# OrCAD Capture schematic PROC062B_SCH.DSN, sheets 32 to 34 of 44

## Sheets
32 31. FT4232 UART TO USB BRIDGE: size C; title: FT4232 UART TO USB BRIDGE
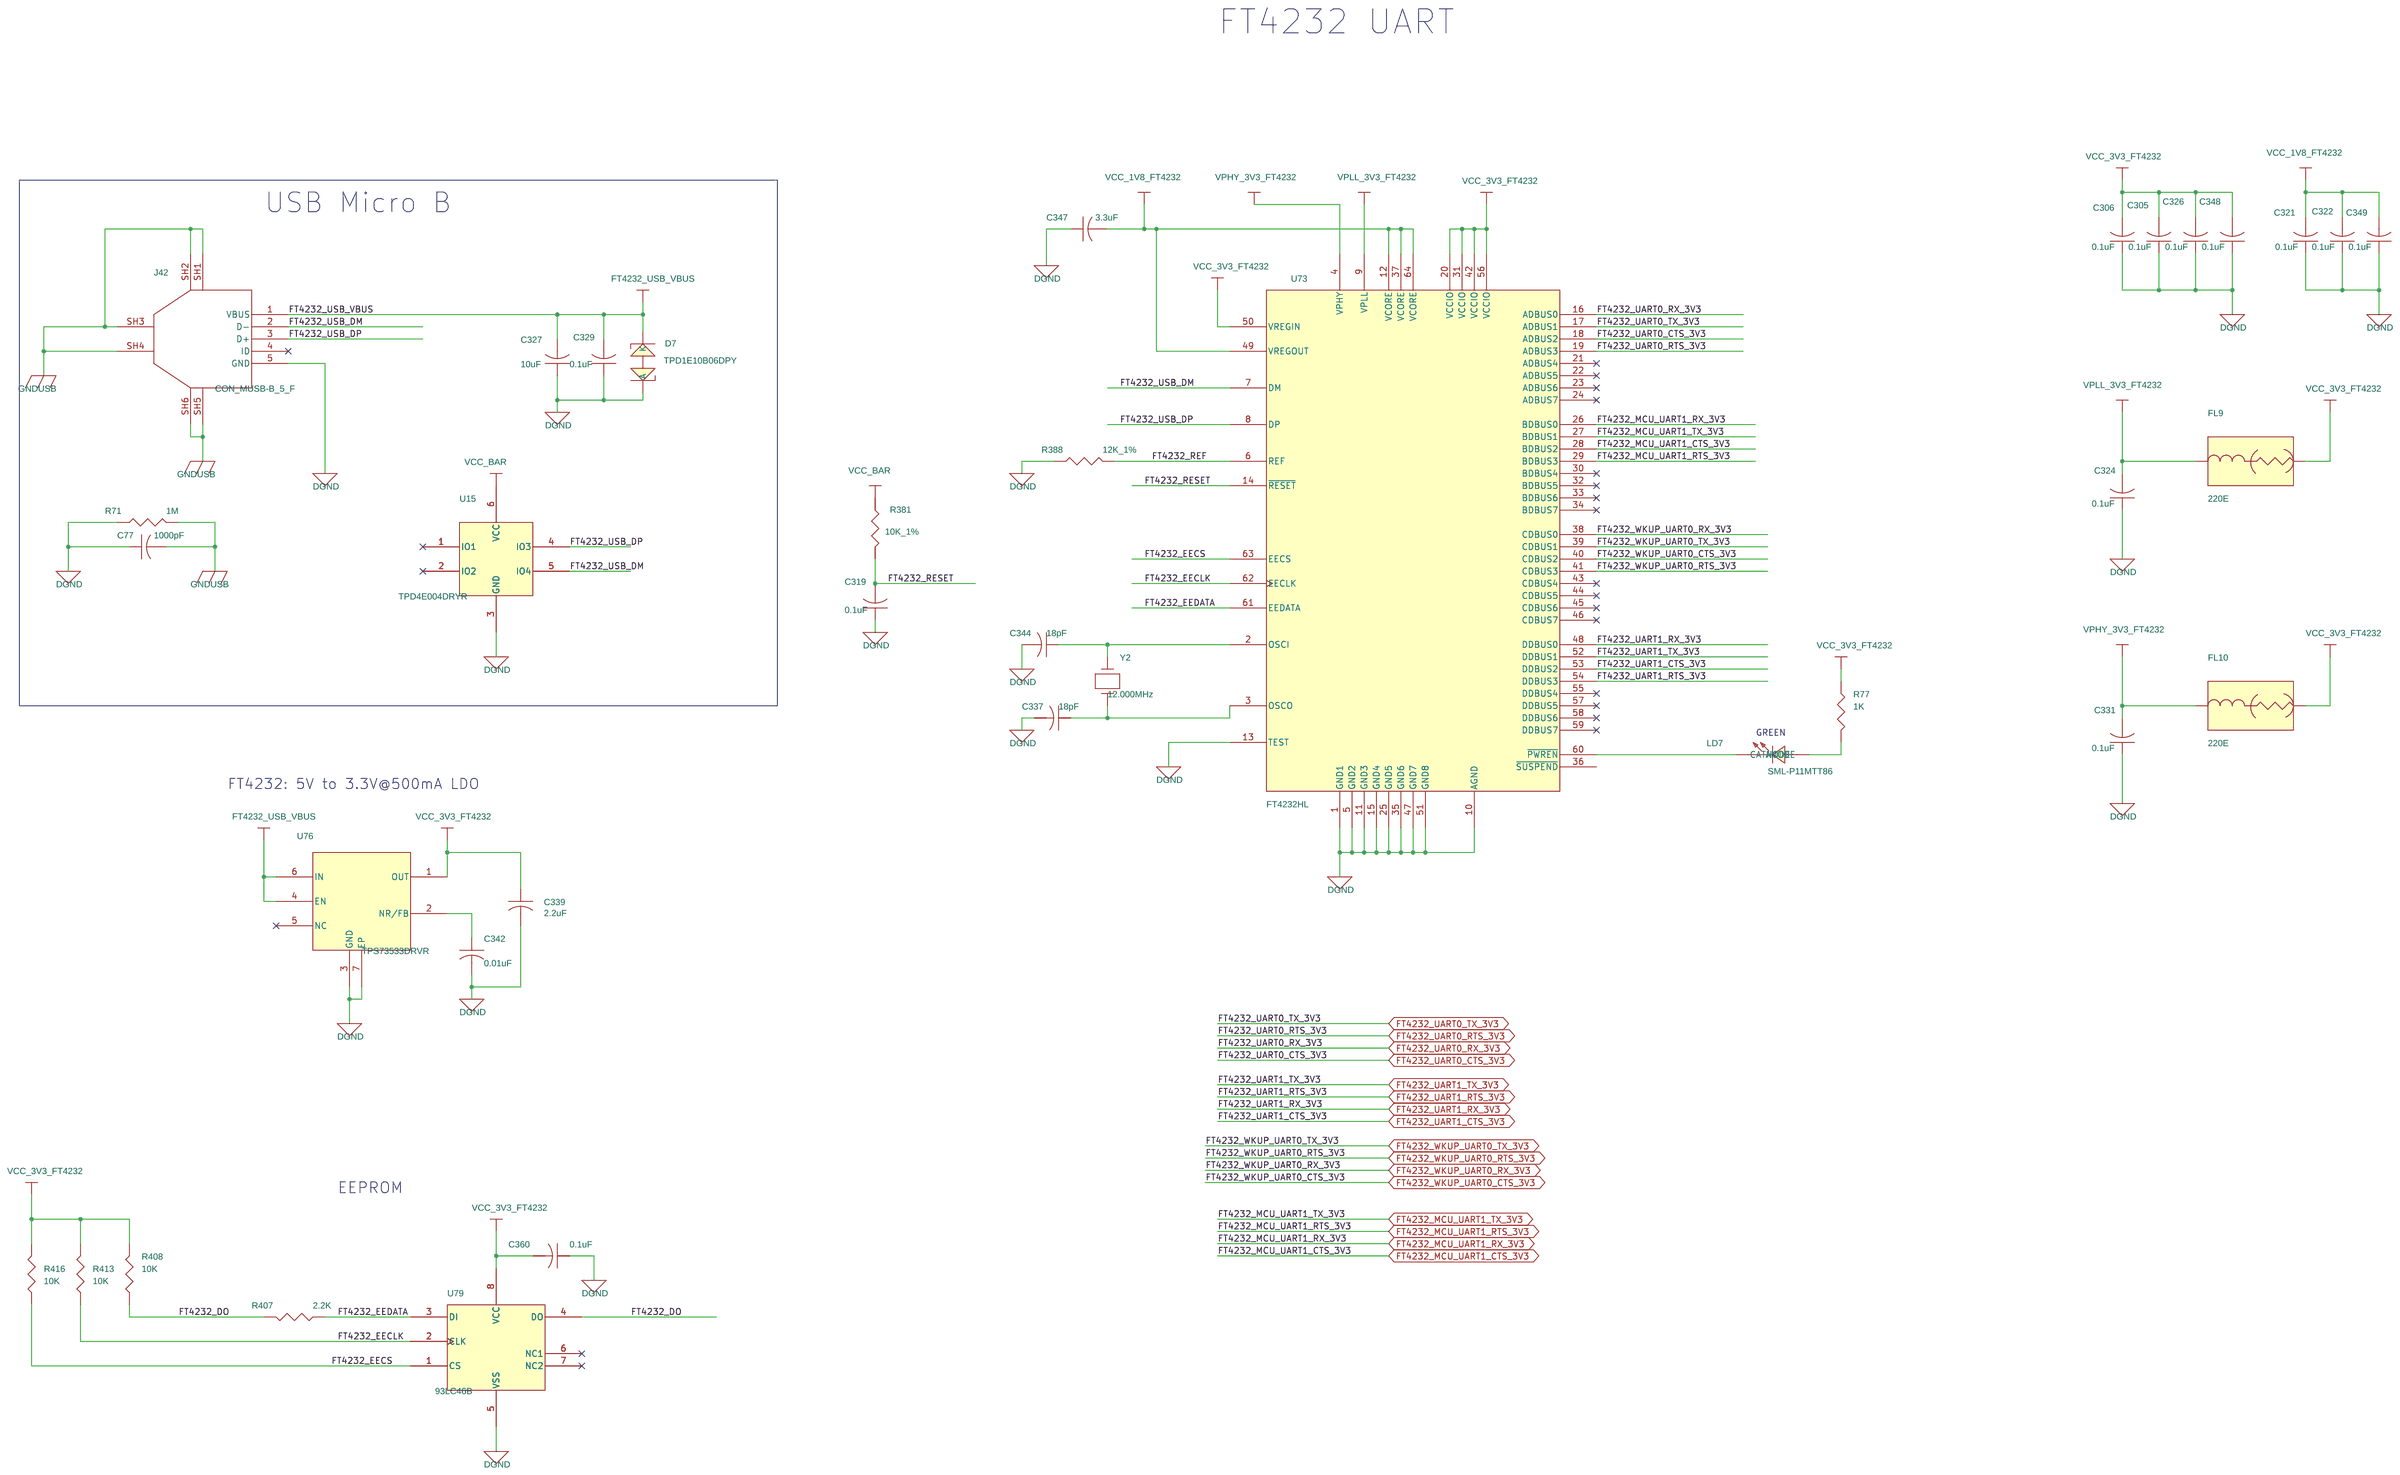
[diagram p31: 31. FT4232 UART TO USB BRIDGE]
33 32.APPLICATION BOARD CONN: size C; title: APPLICATION BOARD CONNECTOR
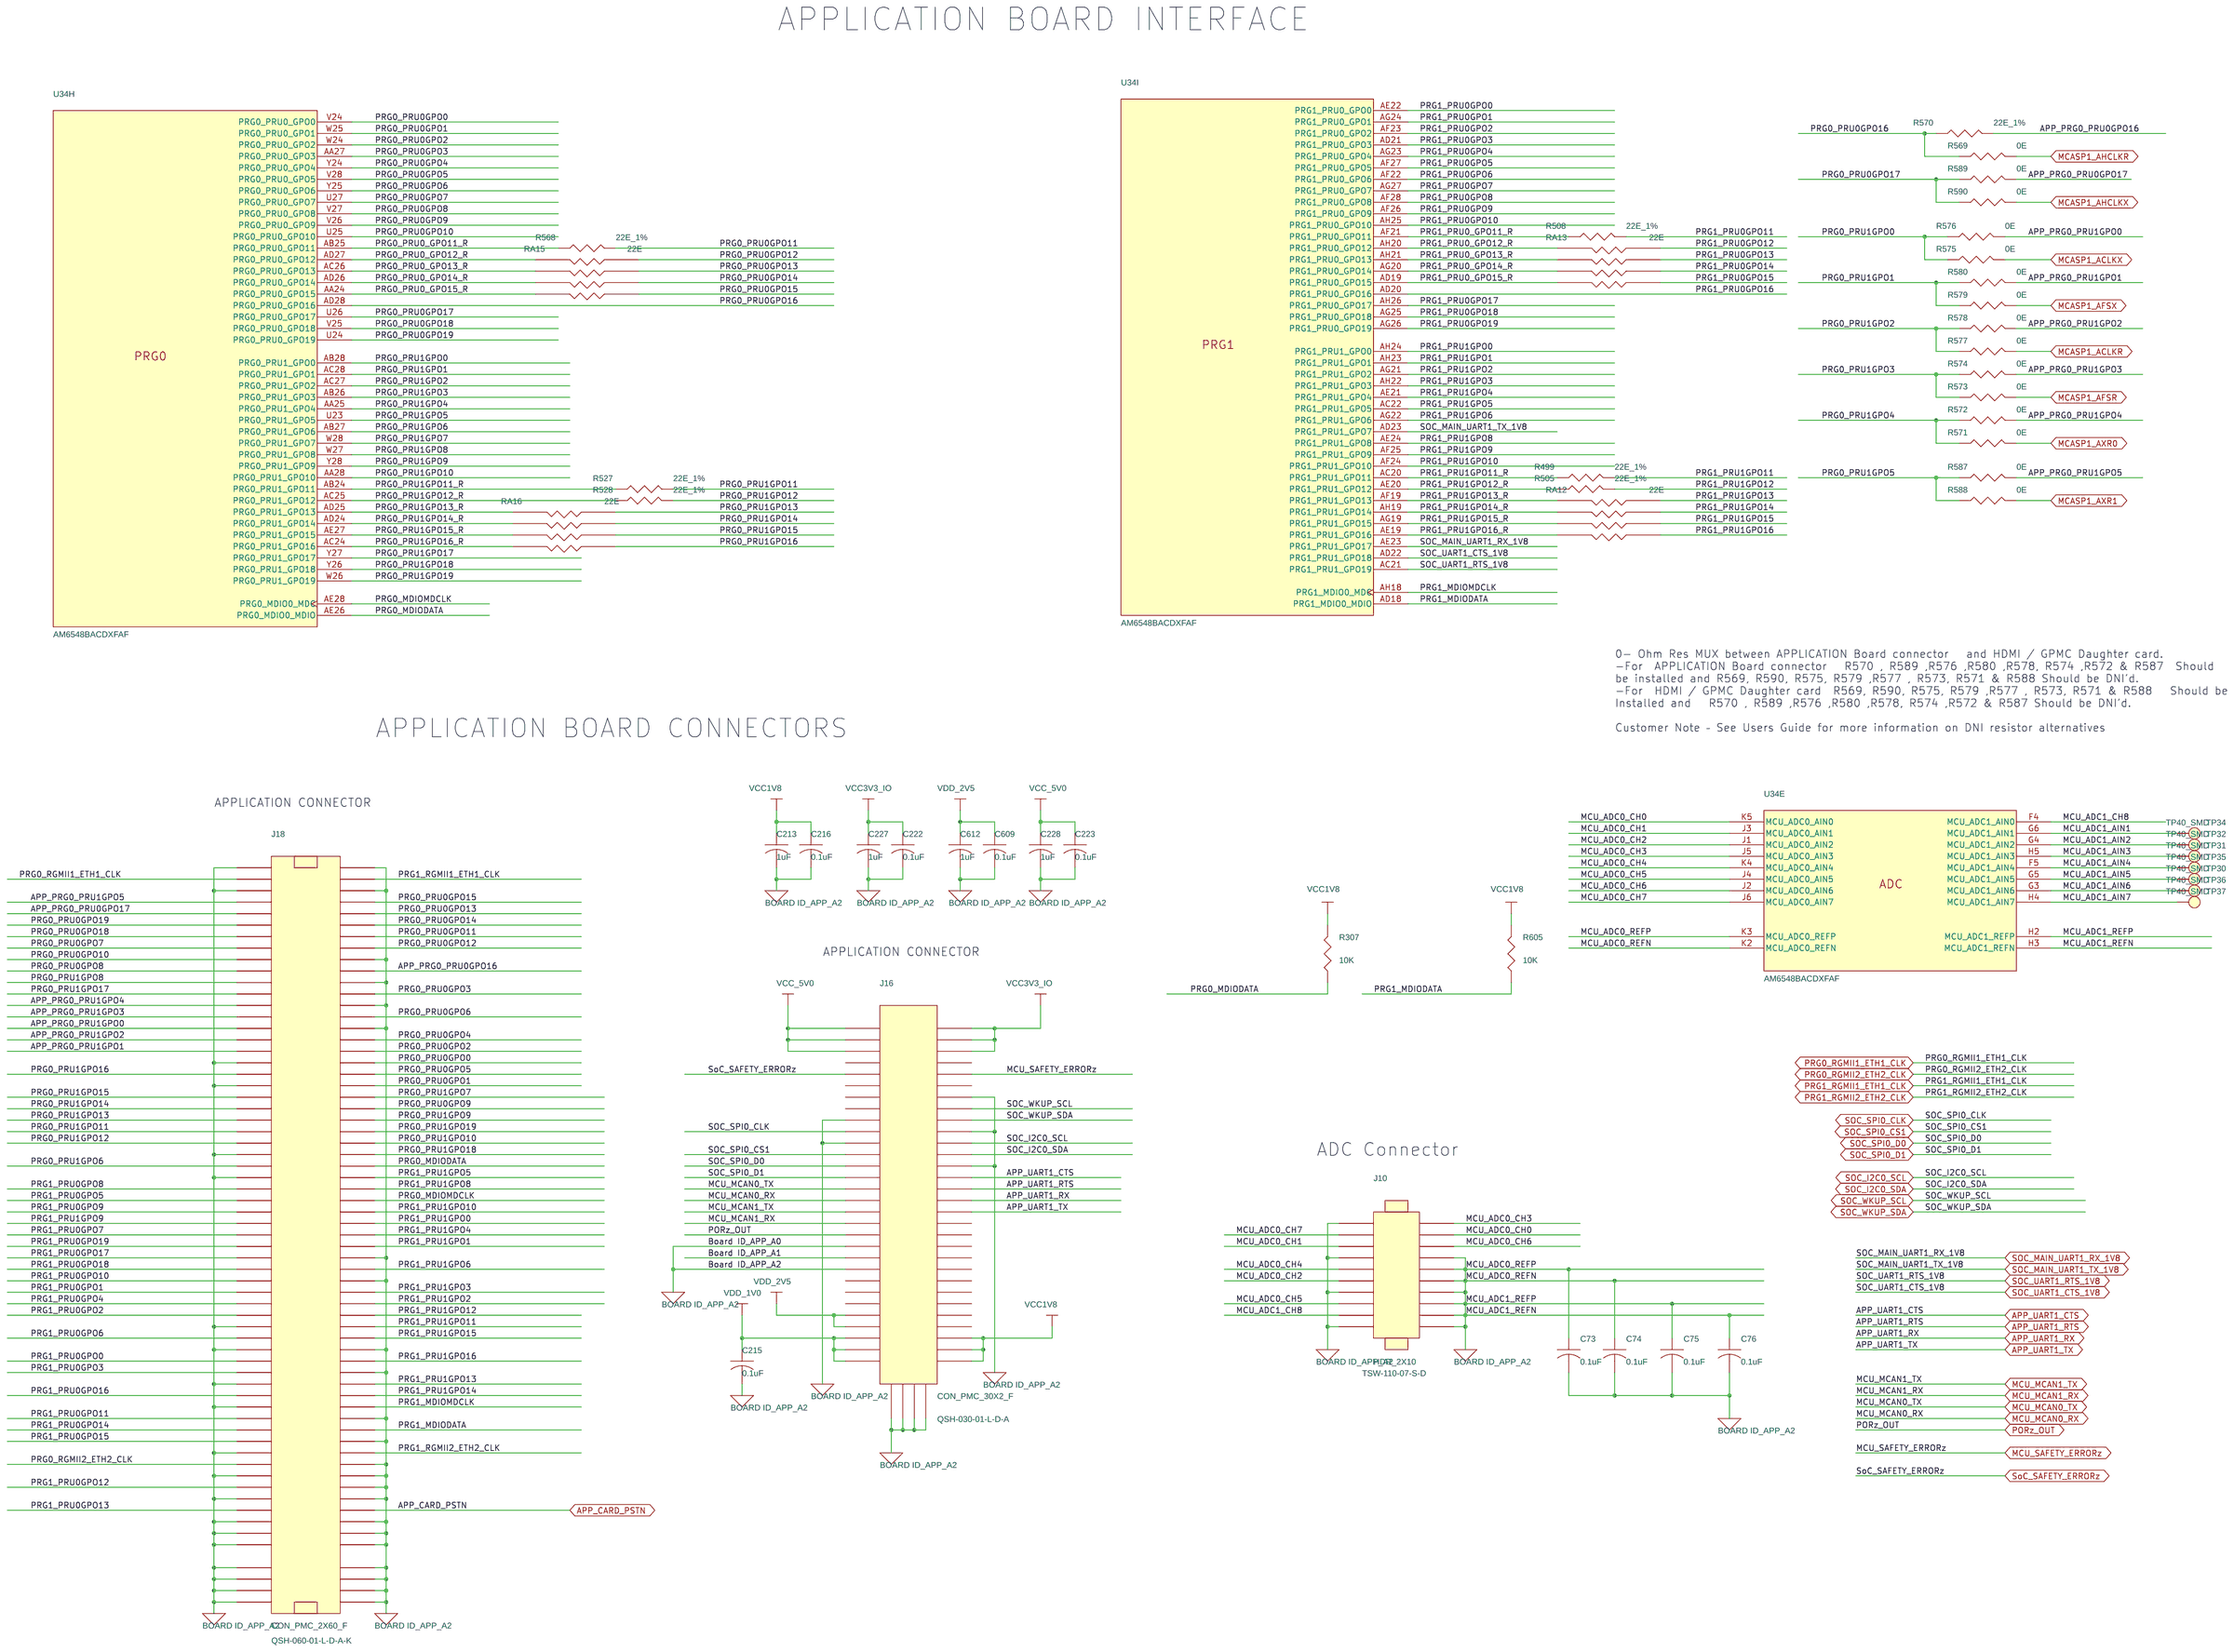
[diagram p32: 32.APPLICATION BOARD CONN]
34 33. GENERAL & MCU_GENERAL INTER: size C; title: SOC_GENERAL & MCU GENERAL
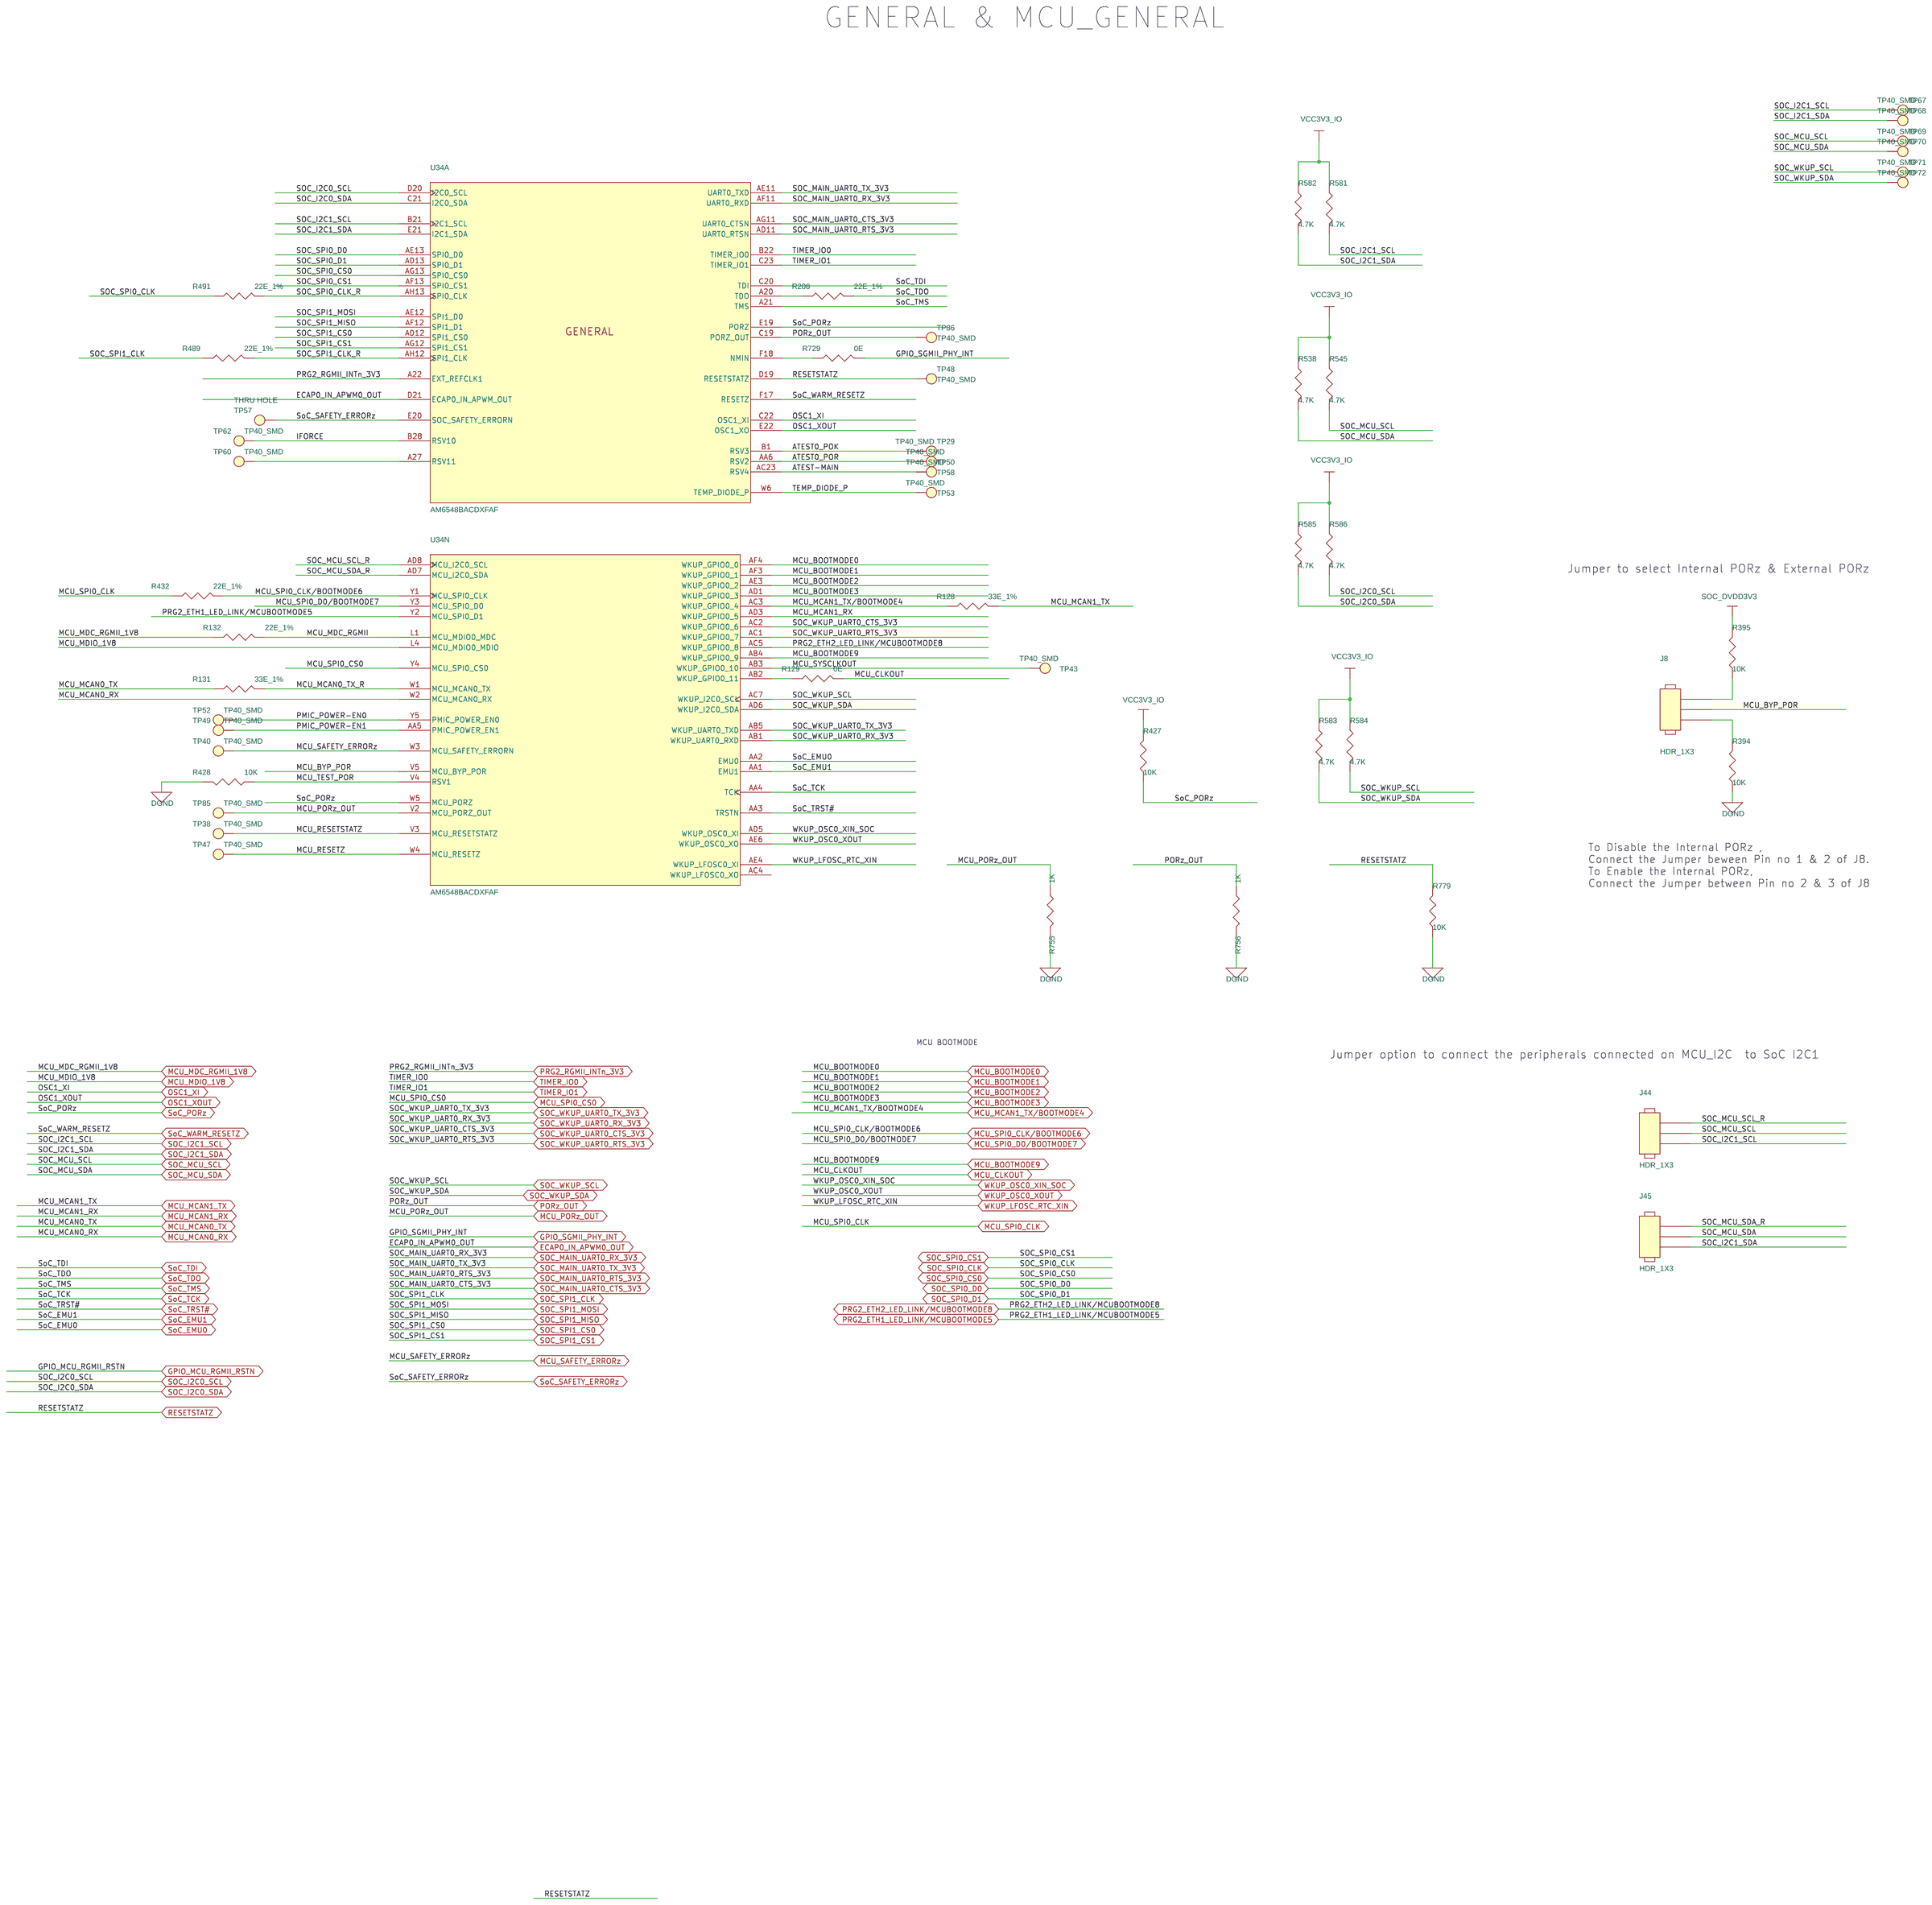
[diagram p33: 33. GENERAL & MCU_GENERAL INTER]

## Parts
sheet 16. DDR4 ECC & TERMINATIONS
U34  AM6548BACDXFAF  [BGA784_31-49_910X910_1-7]  (sections A,B,C,D,E,F,G,H,I,J,K,L,M,N,O,P,Q,R,S)
sheet 31. FT4232 UART TO USB BRIDGE
C77  1000pF  [CAP1206]
C305  0.1uF  [CAP0201_0-5]
C306  0.1uF  [CAP0201_0-5]
C319  0.1uF  [CAP0201_0-5]
C321  0.1uF  [CAP0201_0-5]
C322  0.1uF  [CAP0201_0-5]
C324  0.1uF  [CAP0201_0-5]
C326  0.1uF  [CAP0201_0-5]
C327  10uF  [CAP0603_1]
C329  0.1uF  [CAP0201_0-5]
C331  0.1uF  [CAP0201_0-5]
C337  18pF  [CAP0402_0-75]
C339  2.2uF  [CAP0402_0-75]
C342  0.01uF  [CAP0201_0-5]
C344  18pF  [CAP0402_0-75]
C347  3.3uF  [CAP0402]
C348  0.1uF  [CAP0201_0-5]
C349  0.1uF  [CAP0201_0-5]
C360  0.1uF  [CAP0201_0-5]
D7  TPD1E10B06DPY  [DIO_DFN0402]
FL9  220E  [EMIFIL_BLM15A_0402]
FL10  220E  [EMIFIL_BLM15A_0402]
J42  CON_MUSB-B_5_F  [CON_MUSBB5_1051640001_S_R_S_2-5]
LD7  SML-P11MTT86  [LED_0402_0-3]
R71  1M  [RES0603_0-75]
R77  1K  [RES0201]
R381  10K_1%  [RES0402_0-5]
R388  12K_1%  [RES0402]
R407  2.2K  [RES0402_0-5]
R408  10K  [RES0402_0-5]
R413  10K  [RES0402_0-5]
R416  10K  [RES0402_0-5]
U15  TPD4E004DRYR  [SON6_19-68_60X45]
U73  FT4232HL  [LQFP64_19-68_390X390_1-6]
U76  TPS73533DRVR  [SON6_25-59_85X85]
U79  93LC46B  [MSOP8_25-59_125X125_1-1]
Y2  12.000MHz  [XTAL_ABM3_205X130_SMD_1-4]
sheet 32.APPLICATION BOARD CONN
C73  0.1uF  [CAP0201_0-5]
C74  0.1uF  [CAP0201_0-5]
C75  0.1uF  [CAP0201_0-5]
C76  0.1uF  [CAP0201_0-5]
C213  1uF  [CAP0402_0-75]
C215  0.1uF  [CAP0201_0-5]
C216  0.1uF  [CAP0201_0-5]
C222  0.1uF  [CAP0201_0-5]
C223  0.1uF  [CAP0201_0-5]
C227  1uF  [CAP0402_0-75]
C228  1uF  [CAP0402_0-75]
C609  0.1uF  [CAP0201_0-5]
C612  1uF  [CAP0402_0-75]
J10  HDR_2X10  [HDR_2X10_TSW_100_S_T]
J16  CON_PMC_30X2_F  [CON_PMC30X2_QSH-030-01-L_S_S_S]
J18  CON_PMC_2X60_F  [CON_PMC60X2_HQCD-060_S_S_S_3-3]
R307  10K  [RES0402_0-5]
R499  22E_1%  [RES0402]
R505  22E_1%  [RES0402]
R508  22E_1%  [RES0402]
R527  22E_1%  [RES0402]
R528  22E_1%  [RES0402]
R568  22E_1%  [RES0402]
R569  0E  [RES0402_0-5]
R570  22E_1%  [RES0402]
R571  0E  [RES0402_0-5]
R572  0E  [RES0402_0-5]
R573  0E  [RES0402_0-5]
R574  0E  [RES0402_0-5]
R575  0E  [RES0402_0-5]
R576  0E  [RES0402_0-5]
R577  0E  [RES0402_0-5]
R578  0E  [RES0402_0-5]
R579  0E  [RES0402_0-5]
R580  0E  [RES0402_0-5]
R587  0E  [RES0402_0-5]
R588  0E  [RES0402_0-5]
R589  0E  [RES0402_0-5]
R590  0E  [RES0402_0-5]
R605  10K  [RES0402_0-5]
RA12  22E  [RESA_EXB28V_0402-4_0-5]
RA13  22E  [RESA_EXB28V_0402-4_0-5]
RA15  22E  [RESA_EXB28V_0402-4_0-5]
RA16  22E  [RESA_EXB28V_0402-4_0-5]
TP30  TP40_SMD  [TP40_SMD]
TP31  TP40_SMD  [TP40_SMD]
TP32  TP40_SMD  [TP40_SMD]
TP34  TP40_SMD  [TP40_SMD]
TP35  TP40_SMD  [TP40_SMD]
TP36  TP40_SMD  [TP40_SMD]
TP37  TP40_SMD  [TP40_SMD]
sheet 33. GENERAL & MCU_GENERAL INTER
J8  HDR_1X3  [HDR_3X1_100_S_T]
J44  HDR_1X3  [HDR_3X1_100_S_T]
J45  HDR_1X3  [HDR_3X1_100_S_T]
R128  33E_1%  [RES0402_0-5]
R129  0E  [RES0402_0-5]
R131  33E_1%  [RES0402_0-5]
R132  22E_1%  [RES0402]
R208  22E_1%  [RES0402]
R394  10K  [RES0402_0-5]
R395  10K  [RES0402_0-5]
R427  10K  [RES0402_0-5]
R428  10K  [RES0402_0-5]
R432  22E_1%  [RES0402]
R489  22E_1%  [RES0402]
R491  22E_1%  [RES0402]
R538  4.7K  [RES0402]
R545  4.7K  [RES0402]
R581  4.7K  [RES0402]
R582  4.7K  [RES0402]
R583  4.7K  [RES0402]
R584  4.7K  [RES0402]
R585  4.7K  [RES0402]
R586  4.7K  [RES0402]
R729  0E  [RES0402_0-5]
R755  1K  [RES0402]
R756  1K  [RES0402]
R779  10K  [RES0402_0-5]
TP29  TP40_SMD  [TP40_SMD]
TP38  TP40_SMD  [TP40_SMD]
TP40  TP40_SMD  [TP40_SMD]
TP43  TP40_SMD  [TP40_SMD]
TP47  TP40_SMD  [TP40_SMD]
TP48  TP40_SMD  [TP40_SMD]
TP49  TP40_SMD  [TP40_SMD]
TP50  TP40_SMD  [TP40_SMD]
TP52  TP40_SMD  [TP40_SMD]
TP53  TP40_SMD  [TP40_SMD]
TP57  THRU HOLE  [TP_40X65]
TP58  TP40_SMD  [TP40_SMD]
TP60  TP40_SMD  [TP40_SMD]
TP62  TP40_SMD  [TP40_SMD]
TP67  TP40_SMD  [TP40_SMD]
TP68  TP40_SMD  [TP40_SMD]
TP69  TP40_SMD  [TP40_SMD]
TP70  TP40_SMD  [TP40_SMD]
TP71  TP40_SMD  [TP40_SMD]
TP72  TP40_SMD  [TP40_SMD]
TP85  TP40_SMD  [TP40_SMD]
TP86  TP40_SMD  [TP40_SMD]

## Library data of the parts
U34 = AM654X_BGA784: IC AM65X MICRO CONTROLLER UNIT BGA784; Chkd/date: ALVY/010721; Crtd /date: MANIRAJA/010721; Custom_Duty: 15%; Customs_HS_Code: 85423100; Distributor_name: NA; Distributor_part_number: NA; Footprint Path: Y:\MIS_DATABASE\Library\ALTIUM_TOOL\PCB_FOOTPRINTS\Altium_Footprint_Lib.PcbLib; Height: 1.63MM; Library Path: Y:\MIS_DATABASE\Library\ALTIUM_TOOL\SCHEMATICS_PARTS\MS_MICROCONTROLLER_Library.schlib; Mfr_name: TEXAS INSTRUMENTS; Mistral Part No: 141221070001; Package: BGA784; Part_type: ICS\DIGITAL\MICROCONTROLLER; Project: TI_AM65X_CP; RoHS: NA; Temperature: NA; Tolerance: NA; Voltage: NA; Wattage: NA; Weight: NA; Datasheet: Y:\MIS_DATABASE\DATASHEETS\ICS\DIGITAL\MICROCONTROLLER\MAXWELLM4.PDF
C77 = CAP: CAP CERAMIC 1000pF 2KV 10% X7R 1206; Chkd/date: SHREESHAIL/291106; Crtd /date: MAZHAR/281106; Custom_Duty: 15%; Customs_HS_Code: 85322990; Distributor_name: DIGIKEY; Distributor_part_number: 478-2956-1-ND; Footprint Path: Y:\MIS_DATABASE\Library\ALTIUM_TOOL\PCB_FOOTPRINTS\Altium_Footprint_Lib.PcbLib; Height: 1.50MM; Library Path: Y:\MIS_DATABASE\Library\ALTIUM_TOOL\SCHEMATICS_PARTS\MS_DISCRETE_Library.schlib; Mfr_name: AVX CORPORATION; Mfr_part_number: 1206GC102KAT1A; Mistral Part No: 120009030147-R; Package: 1206; Part_type: CAPACITORS\CERAMIC; Project: ADR1B; RoHS: RoHS; Temperature: -55°C+125°C; Tolerance: 10%; Voltage: 2KV; Weight: NA; Datasheet: Y:\MIS_DATABASE\DATASHEETS\CAPACITORS\AVX_MLC.PDF
C73-C76 C215 C216 C222 C223 C305 C306 C319 C321 C322 C324 C326 C329 C331 C348 C349 C360 C609 = CAP: CAP CERAMIC 0.1uF 16V 10% X5R 0201; Chkd/date: MANIRAJA/120218; Crtd /date: MANIRAJA/120218; Custom_Duty: 15%; Customs_HS_Code: 85322990; Distributor_name: DIGIKEY; Distributor_part_number: 490-16742-1-ND; Height: 0.33MM; Mfr_name: MURATA; Mfr_part_number: GRM033R61C104KE84J; Mistral Part No: 120009030072-R; Package: 0201; Part_type: CAPACITORS\CERAMIC; Project: TI_MAXIE_CPB; RoHS: RoHS; Temperature: -55°C+85°C; Tolerance: 10%; Voltage: 16V; Wattage: NA; Weight: 0.33mg; Datasheet: Y:\MIS_DATABASE\DATASHEETS\CAPACITORS\GRM033R61C104KE84.PDF
C327 = CAP: CAP CERAMIC 10uF 10V 10% X5R 0603; Chkd/date: MANIRAJA/230118; Crtd /date: MANIRAJA/230118; Custom_Duty: 15%; Customs_HS_Code: 85322990; Distributor_name: DIGIKEY; Distributor_part_number: 478-10766-1-ND; Height: 0.94MM; Mfr_name: AVX CORPORATION; Mfr_part_number: 0603ZD106KAT2A; Mistral Part No: 120010080001-R; Package: 0603; Part_type: CAPACITORS\CERAMIC; Project: TI_MAXIE_CPB; RoHS: RoHS; Temperature: -55°C+85°C; Tolerance: 10%; Voltage: 10V; Wattage: NA; Weight: 2mg; Datasheet: Y:\MIS_DATABASE\DATASHEETS\CAPACITORS\AVX_MLC.PDF
C337 C344 = CAP: CAP CERAMIC 18pF 50V 5% C0G(NP0) 0402; Chkd/date: MANIRAJA/070220; Crtd /date: ALVY/070220; Custom_Duty: 15%; Customs_HS_Code: 85322990; Distributor_name: DIGIKEY; Distributor_part_number: 399-8952-1-ND; Footprint Path: Y:\MIS_DATABASE\Library\ALTIUM_TOOL\PCB_FOOTPRINTS\Altium_Footprint_Lib.PcbLib; Height: 0.55MM; Library Path: Y:\MIS_DATABASE\Library\ALTIUM_TOOL\SCHEMATICS_PARTS\MS_DISCRETE_Library.schlib; Mfr_name: KEMET; Mfr_part_number: C0402C180J5GAC7867; Mistral Part No: 120011090034-R; Package: 0402; Part_type: CAPACITORS\CERAMIC; Project: TI_MAXIE_CPB; RoHS: RoHS; Temperature: -55°C+125°C; Tolerance: 5%; Voltage: 50V; Wattage: NA; Weight: 0.65mg; Datasheet: Y:\MIS_DATABASE\DATASHEETS\CAPACITORS\KEMET-C0G_SERIES.PDF
C339 = CAP: CAP CERAMIC 2.2uF 10V 20% X5R 0402; Chkd/date: MANIRAJA/240118; Crtd /date: MANIRAJA/240118; Custom_Duty: 15%; Customs_HS_Code: 85322990; Distributor_name: DIGIKEY; Distributor_part_number: 490-12254-1-ND; Height: 0.55MM; Mfr_name: MURATA; Mfr_part_number: GRT155R61A225ME01D; Mistral Part No: 120018010016-R; Package: 0402; Part_type: CAPACITORS\CERAMIC; Project: TI_MAXIE_CPB; RoHS: RoHS; Temperature: -55°C+85°C; Tolerance: 20%; Voltage: 10V; Wattage: NA; Weight: 0.65mg; Datasheet: Y:\MIS_DATABASE\DATASHEETS\CAPACITORS\GRT155R61A225ME01.PDF
C342 = CAP: CAP CERAMIC 0.01uF 25V 10% X5R 0201; Chkd/date: MANIRAJA/230118; Crtd /date: MANIRAJA/230118; Custom_Duty: 15%; Customs_HS_Code: 85322990; Distributor_name: DIGIKEY; Distributor_part_number: GRM033R61E103KA12J-ND; Height: 0.33MM; Mfr_name: MURATA; Mfr_part_number: GRM033R61E103KA12J; Mistral Part No: 120018010007-R; Package: 0201; Part_type: CAPACITORS\CERAMIC; Project: TI_MAXIE_CPB; RoHS: RoHS; Temperature: -55°C+85°C; Tolerance: 10%; Voltage: 25V; Wattage: NA; Weight: 0.33mg; Datasheet: Y:\MIS_DATABASE\DATASHEETS\CAPACITORS\GRM033R61E103KA12.PDF
C347 = CAP: CAP CERAMIC 3.3uF 6.3V 20% X5R 0402; Chkd/date: NAVEED/270315; Crtd /date: VASANTHA/130215; Custom_Duty: 15%; Customs_HS_Code: 85322990; Distributor_name: DIGIKEY; Distributor_part_number: 445-7394-1-ND; Height: 0.60MM; Mfr_name: TDK CORPORATION; Mfr_part_number: C1005X5R0J335M050BC; Mistral Part No: 120015020002-R; Package: 0402; Part_type: CAPACITORS\CERAMIC; Project: GALILEO_EVM; RoHS: RoHS; Temperature: -55°C+85°C; Tolerance: 20%; Voltage: 6.3V; Wattage: NA; Weight: NA; Datasheet: Y:\MIS_DATABASE\DATASHEETS\CAPACITORS\TDK_CAP.PDF
D7 = DIODE_PESD: DIODE 1CH ESD PROTECTION SMD(0402); Chkd/date: USMAN/021214; Crtd /date: VASANTHA/181114; Custom_Duty: 15%; Customs_HS_Code: 85423100; Distributor_name: DIGIKEY; Distributor_part_number: 296-30406-1-ND; Height: 0.45MM; Mfr_name: TEXAS INSTRUMENTS; Mistral Part No: 130014110022-R; Package: SMD; Part_type: DIODE\MISC; Project: GALILEO_EVM; RoHS: RoHS; Temperature: -40°C+125°C; Tolerance: NA; Voltage: NA; Wattage: NA; Weight: NA; Datasheet: Y:\MIS_DATABASE\DATASHEETS\ICS\INTERFACE\TPD1E10B06.PDF
FL9 FL10 = EMIFILTER_IND: FERRITE CHIP 220E 0.3A 0402; Chkd/date: VASANTHA/270715; Crtd /date: USMAN/151013; Custom_Duty: 15%; Customs_HS_Code: 85412900; Distributor_name: DIGIKEY; Distributor_part_number: 490-5197-1-ND; Height: 0.55MM; Mfr_name: MURATA; Mfr_part_number: BLM15GG221SN1D; Mistral Part No: 130013100020-R; Package: 0402; Part_type: MISC\FILTER; Project: C-BAND_SYNTH; RoHS: RoHS; Temperature: -55°C+125°C; Tolerance: 25%; Voltage: NA; Wattage: NA; Weight: NA; Datasheet: Y:\MIS_DATABASE\DATASHEETS\DISCRETES\INDUCTORS\BLM18K-SERIES.PDF
J42 = CON_MUSB-B_5_1051640001: CON MICRO USB-B TYPE 5POS FEMALE RT SMD; Chkd/date: MANIRAJA/230817; Crtd /date: MANIRAJA/230817; Custom_Duty: 24%; Customs_HS_Code: 85369090; Distributor_name: DIGIKEY; Distributor_part_number: WM11263CT-ND; Height: 2.45MM; Mfr_name: MOLEX; Mfr_part_number: 1051640001; Mistral Part No: 150017080018-R; Package: SMD; Part_type: CONNECTOR\USB; Project: TI_MAXIE_CPB; RoHS: RoHS; Temperature: -35°C+85°C; Tolerance: NA; Voltage: NA; Wattage: NA; Weight: 234mg; Datasheet: Y:\MIS_DATABASE\DATASHEETS\CONNECTORS\1051640001.PDF
LD7 = DIODE_LED: DIODE LED GREEN 0402; Chkd/date: VASANTHA/281216; Crtd /date: MUDDU/190610; Custom_Duty: 24%; Customs_HS_Code: 85439000; Distributor_name: DIGIKEY; Distributor_part_number: 511-1652-1-ND; Footprint Path: Y:\MIS_DATABASE\Library\ALTIUM_TOOL\PCB_FOOTPRINTS\Altium_Footprint_Lib.PcbLib; Height: 0.25MM; Library Path: Y:\MIS_DATABASE\Library\ALTIUM_TOOL\SCHEMATICS_PARTS\MS_DISCRETE_Library.schlib; Mfr_name: ROHM; Mistral Part No: 130010060029-R; Package: 0402; Part_type: OPTO\LED; Project: XMC660; RoHS: RoHS; Temperature: -40°C+85°C; Tolerance: NA; Voltage: NA; Wattage: NA; Weight: NA; Datasheet: Y:\MIS_DATABASE\DATASHEETS\DISCRETES\LEDS\SML-P11.PDF
R71 = RESISTOR: RES 1M 1/10W 5% 0603; Chkd/date: VASANTHA/060217; Crtd /date: USMAN/111207; Custom_Duty: 15%; Customs_HS_Code: 85332119; Distributor_name: DIGIKEY; Distributor_part_number: P1.0MGCT-ND; Height: 0.55MM; Mfr_name: PANASONIC-ECG; Mfr_part_number: ERJ-3GEYJ105V; Mistral Part No: 110009030413-R; Package: 0603; Part_type: RESISTORS\FIXED; Project: BSN; RoHS: RoHS; Temperature: -55°C+155°C; Tolerance: 5%; Voltage: NA; Wattage: 1/10W; Weight: 2mg; Datasheet: Y:\MIS_DATABASE\DATASHEETS\RESISTORS\PAN-ERJ-3GE.PDF
R77 = RESISTOR: RES 1K 1/20W 5% 0201; Chkd/date: JEBRAN/110815; Crtd /date: JEBRAN/110815; Custom_Duty: 15%; Customs_HS_Code: 85332119; Distributor_name: DIGIKEY; Distributor_part_number: 541-1.00KAABCT-ND; Height: 0.28MM; Mfr_name: VISHAY; Mfr_part_number: CRCW02011K00FKED; Mistral Part No: 110015080014-R; Package: 0201; Part_type: RESISTORS\FIXED; Project: OCTASIC_3000; RoHS: RoHS; Temperature: -55°C+155°C; Tolerance: 5%; Voltage: NA; Wattage: 1/20W; Weight: NA; Datasheet: Y:\MIS_DATABASE\DATASHEETS\RESISTORS\CRCW0201.PDF
R381 = RESISTOR: RES 10K 1/16W 1% 0402; Chkd/date: VASANTHA/201216; Crtd /date: GEETHA/290506; Custom_Duty: 15%; Customs_HS_Code: 85332119; Distributor_name: DIGIKEY; Distributor_part_number: 311-10.0KLRTR-ND; Footprint Path: Y:\MIS_DATABASE\Library\ALTIUM_TOOL\PCB_FOOTPRINTS\Altium_Footprint_Lib.PcbLib; Height: 0.40MM; Library Path: Y:\MIS_DATABASE\Library\ALTIUM_TOOL\SCHEMATICS_PARTS\MS_DISCRETE_Library.schlib; Mfr_name: YAGEO AMERICA; Mfr_part_number: RC0402FR-0710KL; Mistral Part No: 110009030220-P; Package: 0402; Part_type: RESISTORS\FIXED; Project: VOCERA; RoHS: Pb-Free; Temperature: -55°C+155°C; Tolerance: 1%; Voltage: NA; Wattage: 1/16W; Weight: 0.65mg; Datasheet: Y:\MIS_DATABASE\DATASHEETS\RESISTORS\YAGEO-RC0402.PDF
R388 = RESISTOR: RES 12K 1/16W 1% 0402; Chkd/date: VASANTHA/041215; Crtd /date: VASANTHA/041215; Custom_Duty: 15%; Customs_HS_Code: 85332119; Distributor_name: DIGIKEY; Distributor_part_number: P12.0KLCT-ND; Height: 0.40MM; Mfr_name: PANASONIC-ECG; Mfr_part_number: ERJ-2RKF1202X; Mistral Part No: 110009030289-R; Package: 0402; Part_type: RESISTORS\FIXED; Project: TI_C5545; RoHS: RoHS; Temperature: -55°C+155°C; Tolerance: 1%; Voltage: NA; Wattage: 1/16W; Weight: NA; Datasheet: Y:\MIS_DATABASE\DATASHEETS\RESISTORS\PAN-ERJSERIES.PDF
R407 = RESISTOR: RES 2.2K 1/16W 5% 0402; Chkd/date: VASANTHA/061216; Crtd /date: BAVISH/021210; Custom_Duty: 15%; Customs_HS_Code: 85332119; Distributor_name: DIGIKEY; Distributor_part_number: 311-2.2KJRCT-ND; Footprint Path: VALUE IS VAILABLE 3 TIMES; Height: 0.40MM; Mfr_name: YAGEO AMERICA; Mfr_part_number: RC0402JR-072K2L; Mistral Part No: 110010120018-R; Package: 0402; Part_type: RESISTORS\FIXED; Project: TE4; RoHS: RoHS; Temperature: -55°C+155°C; Tolerance: 5%; Voltage: NA; Wattage: 1/16W; Weight: 0.65mg; Datasheet: Y:\MIS_DATABASE\DATASHEETS\RESISTORS\YAGEO.PDF
R307 R394 R395 R408 R413 R416 R427 R428 R605 R779 = RESISTOR: RES 10K 1/16W 5% 0402; Chkd/date: VASANTHA/061216; Crtd /date: MAZHAR/230805; Custom_Duty: 15%; Customs_HS_Code: 85332119; Distributor_name: DIGIKEY; Distributor_part_number: 311-10KJRCT-ND; Footprint Path: Y:\MIS_DATABASE\Library\ALTIUM_TOOL\PCB_FOOTPRINTS\Altium_Footprint_Lib.PcbLib; Height: 0.40MM; Library Path: Y:\MIS_DATABASE\Library\ALTIUM_TOOL\SCHEMATICS_PARTS\MS_DISCRETE_Library.schlib; Mfr_name: YAGEO AMERICA; Mfr_part_number: RC0402JR-0710KL; Mistral Part No: 110009030208-R; Package: 0402; Part_type: RESISTORS\FIXED; Project: HSE; RoHS: Pb-Free; Temperature: -55°C+155°C; Tolerance: 5%; Voltage: NA; Wattage: 1/16W; Weight: 0.65mg; Datasheet: Y:\MIS_DATABASE\DATASHEETS\RESISTORS\YAGEO-RC0402.PDF
U15 = TPD4E004_SON6: IC 4CH ESD-PROT ARRAY SON6; Chkd/date: SUHAS/131210; Crtd /date: MUDDU/010310; Custom_Duty: 15%; Customs_HS_Code: 85423100; Distributor_name: DIGIKEY; Distributor_part_number: 296-23618-1-ND; Height: 0.60MM; Mfr_name: TEXAS INSTRUMENTS; Mistral Part No: 141010020012-P; Package: SON6; Part_type: ICS\INTERFACE; Project: BUG_BASE-II; RoHS: Pb-Free; Temperature: -40°C+85°C; Weight: NA; Datasheet: Y:\MIS_DATABASE\DATASHEETS\ICS\INTERFACE\TPD4E004.PDF
U73 = FT4232H__LQFP64: IC HIGH SPEED QUAD USB UART LQFP64; Chkd/date: MANIRAJA/110917; Crtd /date: VIJAYALAKSHMI/120813; Custom_Duty: 15%; Customs_HS_Code: 85423100; Distributor_name: DIGIKEY; Distributor_part_number: 768-1026-1-ND; Height: 1.60MM; Library Ref: FT4232H _LQFP64; Mfr_name: FTDI; Mfr_part_number: FT4232HL-REEL; Mistral Part No: 141013080006-R; Package: LQFP64; Part_type: ICS\DIGITAL\PERIPHERAL; Project: DM37XX; RoHS: RoHS; Temperature: -40°C+85°C; Tolerance: NA; Voltage: NA; Wattage: NA; Weight: 342.7mg; Datasheet: Y:\MIS_DATABASE\DATASHEETS\ICS\DIGITAL\PERIPHERAL\FT4232HX.PDF
U76 = TPS73501DRVR_SON6: IC 500mA LOW DROPOUT REGULATOR SON6; Chkd/date: VASANTHA/280915; Crtd /date: NAVEED/011014; Custom_Duty: 15%; Customs_HS_Code: 85423100; Distributor_name: DIGIKEY; Distributor_part_number: TPS73533DRVR-ND; Height: 0.80MM; Mfr_name: TEXAS INSTRUMENTS; Mistral Part No: 142014100001-R; Package: SON6; Part_type: ICS\POWER\VOLTAGE REGULATOR; Project: BLUETOOTH_WATCH; RoHS: RoHS; Temperature: -40°C+125°C; Tolerance: NA; Voltage: NA; Wattage: NA; Weight: NA; Datasheet: Y:\MIS_DATABASE\DATASHEETS\ICS\POWER\TPS735.PDF
U79 = 93LC46B_MSOP8: IC 1K MICROWIRE COMPATIBLE SERIAL EEPROM MSOP8; Chkd/date: MANIRAJA/150218; Crtd /date: ALVY/150218; Custom_Duty: 15%; Customs_HS_Code: 85423100; Distributor_name: DIGIKEY; Distributor_part_number: 93LC46B-I/MS-ND; Footprint Path: Y:\MIS_DATABASE\Library\ALTIUM_TOOL\PCB_FOOTPRINTS\Altium_Footprint_Lib.PcbLib; Height: 1.10MM; Library Path: Y:\MIS_DATABASE\Library\ALTIUM_TOOL\SCHEMATICS_PARTS\MS_MISCMEMORY_Library.schlib; Mfr_name: MICROCHIP; Mfr_part_number: 93LC46B-I/MS; Mistral Part No: 141118020002-R; Package: MSOP8; Part_type: ICS\DIGITAL\MEMORY; Project: TI_MAXIE_CPB; RoHS: RoHS; Temperature: -40°C+85°C; Tolerance: NA; Voltage: NA; Wattage: NA; Weight: 140mg; Datasheet: Y:\MIS_DATABASE\DATASHEETS\ICS\MEMORY\93LC46B.PDF
Y2 = CRY: CRY 12.000MHz 18pF SMD; Chkd/date: MANIRAJA/310818; Crtd /date: MANIRAJA/310818; Custom_Duty: 24%; Customs_HS_Code: 85439000; Distributor_name: DIGIKEY; Distributor_part_number: CTX1170CT-ND; Footprint Path: Y:\MIS_DATABASE\Library\ALTIUM_TOOL\PCB_FOOTPRINTS\Altium_Footprint_Lib.PcbLib; Height: 1.35MM; Library Path: Y:\MIS_DATABASE\Library\ALTIUM_TOOL\SCHEMATICS_PARTS\MS_DISCRETE_Library.schlib; Mfr_name: CTS; Mfr_part_number: 445I23D12M00000; Mistral Part No: 130018080040-R; Package: SMD; Part_type: CRYSTAL; Project: TI_MAXIE_CPB; RoHS: RoHS; Temperature: -40°C+85°C; Tolerance: NA; Voltage: NA; Wattage: NA; Weight: 50mg; Datasheet: Y:\MIS_DATABASE\DATASHEETS\MISC\CRY_OSC\445.PDF
C213 C227 C228 C612 = CAP: CAP CERAMIC 1uF 16V 20% X5R 0402; Chkd/date: MANIRAJA/150218; Crtd /date: ALVY/150218; Custom_Duty: 15%; Customs_HS_Code: 85322990; Distributor_name: DIGIKEY; Distributor_part_number: 587-5514-1-ND; Footprint Path: Y:\MIS_DATABASE\Library\ALTIUM_TOOL\PCB_FOOTPRINTS\Altium_Footprint_Lib.PcbLib; Height: 0.55MM; Library Path: Y:\MIS_DATABASE\Library\ALTIUM_TOOL\SCHEMATICS_PARTS\MS_DISCRETE_Library.schlib; Mfr_name: TAIYO YUDEN; Mfr_part_number: EMK105BJ105MV-F; Mistral Part No: 120018020006-R; Package: 0402; Part_type: CAPACITORS\CERAMIC; Project: TI_MAXIE_CPB; RoHS: RoHS; Temperature: -55°C+85°C; Tolerance: 20%; Voltage: 16V; Wattage: NA; Weight: 0.65mg; Datasheet: Y:\MIS_DATABASE\DATASHEETS\CAPACITORS\EMK105BJ105MV-F.PDF
J10 = HEADER_10X2: CON HDR 2X10 2.54MM PITCH ST TH; Chkd/date: NAVEED/140515; Crtd /date: MAZHAR/020909; Custom_Duty: 0.24; Customs_HS_Code: 85369090; Distributor_name: DIGIKEY; Distributor_part_number: SAM1032-10-ND; Height: 5.02MM; Mfr_name: SAMTEC; Mfr_part_number: TSW-110-07-S-D; Mistral Part No: 150009090001-R; Package: THRU-HOLE; Part_type: CONNECTOR\HEADERS; Project: SMART VIEW_NVR; RoHS: RoHS; Temperature: NA; Tolerance: NA; Voltage: NA; Wattage: NA; Weight: NA; Datasheet: Y:\MIS_DATABASE\DATASHEETS\CONNECTORS\TSW-106-23-T-S.PDF
J16 = CON_PMC_30X2_F: CON PMC 30X2 0.50MM PITCH FEMALE ST SMD; Chkd/date: MAZHAR/180208; Crtd /date: USMAN/051108; Custom_Duty: 24%; Customs_HS_Code: 85369090; Height: 3.25MM; Mfr_name: SAMTEC; Mfr_part_number: QSH-030-01-L-D-A; Mistral Part No: 150009030606; Package: SMD; Part_type: CONNECTOR\PMC; Project: KHAN_HSST; Datasheet: Y:\MIS_DATABASE\DATASHEETS\CONNECTORS\QSH.PDF
J18 = CON_PMC_60X2_HQCD: CON PMC 2X60 0.50MM PITCH FEMALE ST SMD; Chkd/date: MANIRAJA/230817; Crtd /date: MUDDU/020610; Custom_Duty: 24%; Customs_HS_Code: 85369090; Distributor_name: DIGIKEY; Distributor_part_number: SAM10652-ND; Height: 3.25MM; Mfr_name: SAMTEC; Mfr_part_number: QSH-060-01-L-D-A-K; Mistral Part No: 150010060004-R; Package: SMD; Part_type: CONNECTOR\PMC; Project: CENTAURUS; RoHS: RoHS; Temperature: -55°C+125°C; Tolerance: NA; Voltage: NA; Wattage: NA; Weight: NA; Datasheet: Y:\MIS_DATABASE\DATASHEETS\CONNECTORS\QSH.PDF
R132 R499 R505 R508 R527 R528 R568 R570 = RESISTOR: RES 22E 1/16W 1% 0402; Alternate_mfr_name_A: VISHAY; Alternate_mfr_part_number_A: CRCW040222R0FKED; Chkd/date: SUHAS/290910; Crtd /date: MAZHAR/090909; Cust_part_number: 4700-80047E; Custom_Duty: 15%; Customs_HS_Code: 85332119; Distributor_name: DIGIKEY; Distributor_name_A: DIGIKEY; Distributor_part_number: 311-22.0LRCT-ND; Distributor_part_number_A: 541-22.0LCT-ND; Height: 0.40MM; Mfr_name: YAGEO AMERICA; Mfr_part_number: RC0402FR-0722RL; Mistral Part No: 110009090004-P; Package: 0402; Part_type: RESISTORS\FIXED; Project: VMEFMCD; Remarks: In alternate datasheet it is RoHS COMPLIANT. Y:\MIS_DATABASE\DATASHEETS\RESISTORS\CRCW0402.PDF; RoHS: Pb-Free; Temperature: -55°C+155°C; Tolerance: 1%; Voltage: 50V; Wattage: 1/16W; Weight: 0.8g/1000pcs; Datasheet: Y:\MIS_DATABASE\DATASHEETS\RESISTORS\YAGEO-RC0402.PDF
R129 R569 R571-R580 R587-R590 R729 = RESISTOR: RES 0E 1/16W 0402; Chkd/date: VASANTHA/201216; Crtd /date: MUDDU/190810; Custom_Duty: 15%; Customs_HS_Code: 85332119; Distributor_name: DIGIKEY; Distributor_part_number: 541-0.0JCT-ND; Footprint Path: Y:\MIS_DATABASE\Library\ALTIUM_TOOL\PCB_FOOTPRINTS\Altium_Footprint_Lib.PcbLib; Height: 0.40MM; Library Path: Y:\MIS_DATABASE\Library\ALTIUM_TOOL\SCHEMATICS_PARTS\MS_DISCRETE_Library.schlib; Mfr_name: VISHAY; Mfr_part_number: CRCW04020000Z0ED; Mistral Part No: 110010080019-P; Package: 0402; Part_type: RESISTORS\FIXED; Project: PB_BUGBASE; RoHS: Pb-Free; Temperature: -55°C+155°C; Tolerance: NA; Voltage: NA; Wattage: 1/16W; Weight: 0.65g/1000pcs; Datasheet: Y:\MIS_DATABASE\DATASHEETS\RESISTORS\CRCW0603.PDF
RA12 RA13 RA15 RA16 = RESARR_ISO4: RES ARRAY 22E 31mW 5% 0402; Chkd/date: MAZHAR/291208; Crtd /date: USMAN/261108; Distributor_name: DIGIKEY; Distributor_part_number: Y7220CT-ND; Height: 0.45MM; Mfr_name: PANASONIC-ECG; Mfr_part_number: EXB-28V220JX; Mistral Part No: 110009030021-R; Package: 0402; Part_type: RESISTORS\ARRAY; Project: KHAN_MAIN; RoHS: RoHS; Temperature: -55°C+125°C; Tolerance: 5%; Voltage: NA; Wattage: 31mW; Weight: 2mg; Datasheet: Y:\MIS_DATABASE\DATASHEETS\RESISTORS\EXB-2HV.PDF
TP29-TP32 TP34-TP38 TP40 TP43 TP47-TP50 TP52 TP53 TP58 TP60 TP62 TP67-TP72 TP85 TP86 = TESTPOINT: TESTPOINT CIR 40 SMD; Chkd/date: MAZHAR/190505; Crtd /date: MAZHAR/190505; Distributor_name: NA; Distributor_part_number: NA; Footprint Path: Y:\MIS_DATABASE\Library\ALTIUM_TOOL\PCB_FOOTPRINTS\Altium_Footprint_Lib.PcbLib; Height: NA; Library Path: Y:\MIS_DATABASE\Library\ALTIUM_TOOL\SCHEMATICS_PARTS\MS_DISCRETE_Library.schlib; MECHANICAL 3D STEP FILE: NA; Mfr_name: LOCAL; Mistral Part No: 130009030933; Package: SMD; Project: RAINIER-3; RoHS: NA; Temperature: NA; Tolerance: NA; Voltage: NA; Wattage: NA; Weight: NA; Datasheet: NA
J8 J44 J45 = HEADER_3X1: HDR 1X3 2.54MM PITCH ST TH; Chkd/date: VASANTHA/290616; Crtd /date: VASANTHA/290616; Custom_Duty: 15%; Customs_HS_Code: 85322990; Distributor_name: DIGIKEY; Distributor_part_number: 609-3471-ND; Height: 8.58MM; Mfr_name: FCI; Mfr_part_number: 68001-403HLF; Mistral Part No: 150016060025-R; Package: THRU-HOLE; Part_type: CONNECTOR\HEADERS; Project: IKEYP; RoHS: RoHS; Temperature: -40°C+105°C; Tolerance: NA; Voltage: NA; Wattage: NA; Weight: NA; Datasheet: Y:\MIS_DATABASE\DATASHEETS\CONNECTORS\68000.PDF
R128 R131 = RESISTOR: RES 33E 1/16W 1% 0402; Chkd/date: VASANTHA/061216; Crtd /date: JEBRAN/171114; Custom_Duty: 15%; Customs_HS_Code: 85332119; Distributor_name: DIGIKEY; Distributor_part_number: P33.0LCT-ND; Height: 0.40MM; Mfr_name: PANASONIC-ECG; Mfr_part_number: ERJ-2RKF33R0X; Mistral Part No: 110014110006-R; Package: 0402; Part_type: RESISTORS\FIXED; Project: ZK BIOMETRIC; RoHS: RoHS; Temperature: -55°C+125°C; Tolerance: 1%; Voltage: NA; Wattage: 1/16W; Weight: 0.8g/1000pcs; Datasheet: Y:\MIS_DATABASE\DATASHEETS\RESISTORS\PAN-ERJSERIES.PDF
R208 R432 R489 R491 = RESISTOR: RES 22E 1/16W 1% 0402; Alternate_mfr_name_A: VISHAY; Alternate_mfr_part_number_A: CRCW040222R0FKED; Chkd/date: SUHAS/290910; Crtd /date: MAZHAR/090909; Cust_part_number: 4700-80047E; Custom_Duty: 15%; Customs_HS_Code: 85332119; Distributor_name: DIGIKEY; Distributor_name_A: DIGIKEY; Distributor_part_number: 311-22.0LRCT-ND; Distributor_part_number_A: 541-22.0LCT-ND; Height: 0.40MM; Mfr_name: YAGEO AMERICA; Mfr_part_number: RC0402FR-0722RL; Mistral Part No: 110009090004-P; Package: 0402; Part_type: RESISTORS\FIXED; Project: VMEFMCD; Remarks: In alternate datasheet it is RoHS COMPLIANT. Y:\MIS_DATABASE\DATASHEETS\RESISTORS\CRCW0402.PDF; RoHS: Pb-Free; SIGNAL_MODEL: RESISTOR_RES0402_22E_22E; Temperature: -55°C+155°C; Tolerance: 1%; Voltage: 50V; Wattage: 1/16W; Weight: 0.8g/1000pcs; Datasheet: Y:\MIS_DATABASE\DATASHEETS\RESISTORS\YAGEO-RC0402.PDF
R538 R545 R581-R586 = RESISTOR: RES 4.7K 1/16W 5% 0402; Chkd/date: VASANTHA/130516; Crtd /date: VASANTHA/130516; Custom_Duty: 15%; Customs_HS_Code: 85332119; Distributor_name: DIGIKEY; Distributor_part_number: 311-4.7KJRCT-ND; Height: 0.55MM; Mfr_name: YAGEO AMERICA; Mfr_part_number: RC0402JR-074K7L; Mistral Part No: 110009030792-R; Package: 0402; Part_type: RESISTORS\FIXED; Project: TMDXCSK368; RoHS: RoHS; Temperature: -55°C+155°C; Tolerance: 5%; Voltage: NA; Wattage: 1/16W; Weight: NA; Datasheet: Y:\MIS_DATABASE\DATASHEETS\RESISTORS\YAGEO-RC0402.PDF
R755 R756 = RESISTOR: RES 1K 1/16W 5% 0402; Crtd /date: BAVISH/021210; Distributor_name: DIGIKEY; Distributor_part_number: 541-1.0KJCT-ND; Footprint Path: VALUE IS VAILABLE 2 TIMES; Height: 0.40MM; Mfr_name: VISHAY; Mfr_part_number: CRCW04021K00JNED; Mistral Part No: 110010120017-R; Package: 0402; Part_type: RESISTORS\FIXED; Project: TE4; RoHS: RoHS; Temperature: -55°C+155°C; Tolerance: 5%; Voltage: NA; Wattage: 1/16W; Weight: NA; Datasheet: Y:\MIS_DATABASE\DATASHEETS\RESISTORS\CRCW0603.PDF
TP57 = TESTPOINT: TESTPOINT 1.0MM DRILL PTH; Chkd/date: MAZHAR/271211; Crtd /date: SHREESHAIL/041005; Distributor_name: NA; Distributor_part_number: NA; Height: NA; Mfr_name: LOCAL; Mistral Part No: 130009030938; Package: THRU-HOLE; Part_type: MISC\TESTPOINT; Project: HSE; Datasheet: NA

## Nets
DGND: C73.2 C74.2 C75.2 C76.2 C77.1 C213.2 C215.2 C216.2 C222.2 C223.2 C227.2 C228.2 C305.1 C306.1 C319.1 C321.1 C322.1 C324.1 C326.1 C327.1 C329.1 C331.1 C337.2 C339.2 C342.2 C344.2 C347.1 C348.1 C349.1 C360.1 C609.2 C612.2 D7.2(A) J10.1 J10.7 J10.8 J10.13 J10.14 J10.19 J10.20 J16.13 J16.18 J16.19 J16.22 J16.25 J16.40 J16.44 J16.61 J16.62 J16.63 J16.64 J18.1 J18.2 J18.5 J18.6 J18.17 J18.21 J18.25 J18.29 J18.36 J18.40 J18.52 J18.56 J18.69 J18.73 J18.82 J18.85 J18.86 J18.89 J18.92 J18.96 J18.97 J18.101 J18.104 J18.105 J18.107 J18.108 J18.109 J18.111 J18.112 J18.115 J18.116 J18.117 J18.118 J18.119 J18.120 J18.121 J18.122 J18.123 J18.124 J18.125 J18.126 J18.127 J18.128 J42.5(GND) R71.1 R388.1 R394.1 R428.2 R755.2 R756.2 R779.1 U15.3(GND) U73.1(GND1) U73.5(GND2) U73.10(AGND) U73.11(GND3) U73.13(TEST) U73.15(GND4) U73.25(GND5) U73.35(GND6) U73.47(GND7) U73.51(GND8) U76.3(GND) U76.7(EP) U79.5(VSS) ; also on sheet 11 12 13 14 15 16 17 18 19 20 21 22 23 24 25 26 27 28 29 30 31 35 36 37 38 39 40 41 42 43 44
GNDUSB: C77.2 J42.SH1 J42.SH2 J42.SH3 J42.SH4 J42.SH5 J42.SH6 R71.2
VCC1V8: C213.1 C216.1 J16.55 J16.57 J16.59 R307.2 R605.2 ; also on sheet 11 18 19 20 21 22 23 26 29 31 35 36 37 38 41 44
VCC3V3_IO: C222.1 C227.1 J16.1 J16.3 J16.5 R427.2 R538.1 R545.1 R581.1 R582.1 R583.1 R584.1 R585.1 R586.1 ; also on sheet 11 18 19 20 21 22 23 24 25 26 28 29 30 31 35 36 37 38 39 41 42 43 44
VCC_1V8_FT4232: C321.2 C322.2 C347.2 C349.2 U73.12(VCORE) U73.37(VCORE) U73.49(VREGOUT) U73.64(VCORE)
VCC_3V3_FT4232: C305.2 C306.2 C326.2 C339.1 C348.2 C360.2 FL9.2 FL10.2 R77.1 R408.2 R413.2 R416.2 U73.20(VCCIO) U73.31(VCCIO) U73.42(VCCIO) U73.50(VREGIN) U73.56(VCCIO) U76.1(OUT) U79.8(VCC) ; also on sheet 31
VCC_5V0: C223.1 C228.1 J16.2 J16.4 J16.6 ; also on sheet 30 35 40 44
VDD_1V0: C215.1 J16.56 J16.58 J16.60 ; also on sheet 13 21 22 23 35 42
VDD_2V5: C609.1 C612.1 J16.52 J16.54 ; also on sheet 21 22 23 42
APP_CARD_PSTN: J18.113 ; also on sheet 20
APP_PRG0_PRU0GPO16: J18.19 R570.2
APP_PRG0_PRU0GPO17: J18.10 R589.2
APP_PRG0_PRU1GPO0: J18.30 R576.2
APP_PRG0_PRU1GPO1: J18.34 R580.2
APP_PRG0_PRU1GPO2: J18.32 R578.2
APP_PRG0_PRU1GPO3: J18.28 R574.2
APP_PRG0_PRU1GPO4: J18.26 R572.2
APP_PRG0_PRU1GPO5: J18.8 R587.2
APP_UART1_CTS: J16.27 ; also on sheet 31
APP_UART1_RTS: J16.29 ; also on sheet 31
APP_UART1_RX: J16.31 ; also on sheet 31
APP_UART1_TX: J16.33 ; also on sheet 31
ATEST0_POK: TP29.1(TP) U34.B1(RSV3)
ATEST0_POR: TP50.1(TP) U34.AA6(RSV2)
ATEST-MAIN: TP58.1(TP) U34.AC23(RSV4)
Board ID_APP_A1: J16.42
ECAP0_IN_APWM0_OUT: U34.D21(ECAP0_IN_APWM_OUT) ; also on sheet 35
FT4232_DO: R407.2 R408.1 U79.4(DO)
FT4232_EECLK: R413.1 U73.62(EECLK) U79.2(CLK)
FT4232_EECS: R416.1 U73.63(EECS) U79.1(CS)
FT4232_EEDATA: R407.1 U73.61(EEDATA) U79.3(DI)
FT4232_MCU_UART1_CTS_3V3: U73.28(BDBUS2) ; also on sheet 31
FT4232_MCU_UART1_RTS_3V3: U73.29(BDBUS3) ; also on sheet 31
FT4232_MCU_UART1_RX_3V3: U73.26(BDBUS0) ; also on sheet 31
FT4232_MCU_UART1_TX_3V3: U73.27(BDBUS1) ; also on sheet 31
FT4232_REF: R388.2 U73.6(REF)
FT4232_RESET: C319.2 R381.1 U73.14(~{RESET})
FT4232_UART0_CTS_3V3: U73.18(ADBUS2) ; also on sheet 31
FT4232_UART0_RTS_3V3: U73.19(ADBUS3) ; also on sheet 31
FT4232_UART0_RX_3V3: U73.16(ADBUS0) ; also on sheet 31
FT4232_UART0_TX_3V3: U73.17(ADBUS1) ; also on sheet 31
FT4232_UART1_CTS_3V3: U73.53(DDBUS2) ; also on sheet 31
FT4232_UART1_RTS_3V3: U73.54(DDBUS3) ; also on sheet 31
FT4232_UART1_RX_3V3: U73.48(DDBUS0) ; also on sheet 31
FT4232_UART1_TX_3V3: U73.52(DDBUS1) ; also on sheet 31
FT4232_USB_DM: J42.2(D-) U15.5(IO4) U73.7(DM)
FT4232_USB_DP: J42.3(D+) U15.4(IO3) U73.8(DP)
FT4232_USB_VBUS: C327.2 C329.2 D7.1(K) J42.1(VBUS) U15.6(VCC) U76.4(EN) U76.6(IN)
FT4232_WKUP_UART0_CTS_3V3: U73.40(CDBUS2) ; also on sheet 31
FT4232_WKUP_UART0_RTS_3V3: U73.41(CDBUS3) ; also on sheet 31
FT4232_WKUP_UART0_RX_3V3: U73.38(CDBUS0) ; also on sheet 31
FT4232_WKUP_UART0_TX_3V3: U73.39(CDBUS1) ; also on sheet 31
GPIO_SGMII_PHY_INT: R729.2 ; also on sheet 35
IFORCE: TP62.1(TP) U34.B28(RSV10)
MCASP1_ACLKR: R577.2 ; also on sheet 44
MCASP1_ACLKX: R575.2 ; also on sheet 44
MCASP1_AFSR: R573.2 ; also on sheet 44
MCASP1_AFSX: R579.2 ; also on sheet 44
MCASP1_AHCLKR: R569.2 ; also on sheet 44
MCASP1_AHCLKX: R590.2 ; also on sheet 44
MCASP1_AXR0: R571.2 ; also on sheet 44
MCASP1_AXR1: R588.2 ; also on sheet 44
MCU_ADC0_CH0: J10.4 U34.K5(MCU_ADC0_AIN0)
MCU_ADC0_CH1: J10.5 U34.J3(MCU_ADC0_AIN1)
MCU_ADC0_CH2: J10.11 U34.J1(MCU_ADC0_AIN2)
MCU_ADC0_CH3: J10.2 U34.J5(MCU_ADC0_AIN3)
MCU_ADC0_CH4: J10.9 U34.K4(MCU_ADC0_AIN4)
MCU_ADC0_CH5: J10.15 U34.J4(MCU_ADC0_AIN5)
MCU_ADC0_CH6: J10.6 U34.J2(MCU_ADC0_AIN6)
MCU_ADC0_CH7: J10.3 U34.J6(MCU_ADC0_AIN7)
MCU_ADC0_REFN: C74.1 J10.12 U34.K2(MCU_ADC0_REFN)
MCU_ADC0_REFP: C73.1 J10.10 U34.K3(MCU_ADC0_REFP)
MCU_ADC1_AIN1: TP34.1(TP) U34.G6(MCU_ADC1_AIN1)
MCU_ADC1_AIN2: TP32.1(TP) U34.G4(MCU_ADC1_AIN2)
MCU_ADC1_AIN3: TP31.1(TP) U34.H5(MCU_ADC1_AIN3)
MCU_ADC1_AIN4: TP35.1(TP) U34.F5(MCU_ADC1_AIN4)
MCU_ADC1_AIN5: TP30.1(TP) U34.G5(MCU_ADC1_AIN5)
MCU_ADC1_AIN6: TP36.1(TP) U34.G3(MCU_ADC1_AIN6)
MCU_ADC1_AIN7: TP37.1(TP) U34.H4(MCU_ADC1_AIN7)
MCU_ADC1_CH8: J10.17 U34.F4(MCU_ADC1_AIN0)
MCU_ADC1_REFN: C76.1 J10.18 U34.H3(MCU_ADC1_REFN)
MCU_ADC1_REFP: C75.1 J10.16 U34.H2(MCU_ADC1_REFP)
MCU_BOOTMODE0: U34.AF4(WKUP_GPIO0_0) ; also on sheet 25 37
MCU_BOOTMODE1: U34.AF3(WKUP_GPIO0_1) ; also on sheet 25 37
MCU_BOOTMODE2: U34.AE3(WKUP_GPIO0_2) ; also on sheet 25
MCU_BOOTMODE3: U34.AD1(WKUP_GPIO0_3) ; also on sheet 25
MCU_BOOTMODE9: U34.AB4(WKUP_GPIO0_9) ; also on sheet 25
MCU_BYP_POR: J8.2 U34.V5(MCU_BYP_POR)
MCU_CLKOUT: R129.2 ; also on sheet 36
MCU_MCAN0_RX: J16.32 U34.W2(MCU_MCAN0_RX)
MCU_MCAN0_TX: J16.30 R131.1
MCU_MCAN0_TX_R: R131.2 U34.W1(MCU_MCAN0_TX)
MCU_MCAN1_RX: J16.36 U34.AD3(WKUP_GPIO0_5)
MCU_MCAN1_TX: J16.34 R128.2
MCU_MCAN1_TX/BOOTMODE4: R128.1 U34.AC3(WKUP_GPIO0_4) ; also on sheet 25
MCU_MDC_RGMII: R132.2 U34.L1(MCU_MDIO0_MDC)
MCU_MDC_RGMII_1V8: R132.1 ; also on sheet 23
MCU_MDIO_1V8: U34.L4(MCU_MDIO0_MDIO) ; also on sheet 23
MCU_PORz_OUT: R755.1 TP85.1(TP) U34.V2(MCU_PORZ_OUT) ; also on sheet 23
MCU_RESETSTATZ: TP38.1(TP) U34.V3(MCU_RESETSTATZ)
MCU_RESETZ: TP47.1(TP) U34.W4(MCU_RESETZ)
MCU_SAFETY_ERRORz: J16.9 TP40.1(TP) U34.W3(MCU_SAFETY_ERRORN)
MCU_SPI0_CLK: R432.1 ; also on sheet 44
MCU_SPI0_CLK/BOOTMODE6: R432.2 U34.Y1(MCU_SPI0_CLK) ; also on sheet 25
MCU_SPI0_CS0: U34.Y4(MCU_SPI0_CS0) ; also on sheet 44
MCU_SPI0_D0/BOOTMODE7: U34.Y3(MCU_SPI0_D0) ; also on sheet 25 44
MCU_SYSCLKOUT: TP43.1(TP) U34.AB3(WKUP_GPIO0_10)
MCU_TEST_POR: R428.1 U34.V4(RSV1)
OSC1_XI: U34.C22(OSC1_XI) ; also on sheet 11
OSC1_XOUT: U34.E22(OSC1_XO) ; also on sheet 11
PMIC_POWER-EN0: TP52.1(TP) U34.Y5(PMIC_POWER_EN0)
PMIC_POWER-EN1: TP49.1(TP) U34.AA5(PMIC_POWER_EN1)
PORz_OUT: J16.38 R756.1 TP86.1(TP) U34.C19(PORZ_OUT) ; also on sheet 19 21 25 35 44
PRG0_MDIODATA: J18.53 R307.1 U34.AE26(PRG0_MDIO0_MDIO)
PRG0_MDIOMDCLK: J18.59 U34.AE28(PRG0_MDIO0_MDC)
PRG0_PRU0_GPO11_R: R568.1 U34.AB25(PRG0_PRU0_GPO11)
PRG0_PRU0_GPO12_R: RA15.5 U34.AD27(PRG0_PRU0_GPO12)
PRG0_PRU0_GPO13_R: RA15.6 U34.AC26(PRG0_PRU0_GPO13)
PRG0_PRU0_GPO14_R: RA15.7 U34.AD26(PRG0_PRU0_GPO14)
PRG0_PRU0_GPO15_R: RA15.8 U34.AA24(PRG0_PRU0_GPO15)
PRG0_PRU0GPO0: J18.35 U34.V24(PRG0_PRU0_GPO0)
PRG0_PRU0GPO1: J18.39 U34.W25(PRG0_PRU0_GPO1)
PRG0_PRU0GPO2: J18.33 U34.W24(PRG0_PRU0_GPO2)
PRG0_PRU0GPO3: J18.23 U34.AA27(PRG0_PRU0_GPO3)
PRG0_PRU0GPO4: J18.31 U34.Y24(PRG0_PRU0_GPO4)
PRG0_PRU0GPO5: J18.37 U34.V28(PRG0_PRU0_GPO5)
PRG0_PRU0GPO6: J18.27 U34.Y25(PRG0_PRU0_GPO6)
PRG0_PRU0GPO7: J18.16 U34.U27(PRG0_PRU0_GPO7)
PRG0_PRU0GPO8: J18.20 U34.V27(PRG0_PRU0_GPO8)
PRG0_PRU0GPO9: J18.43 U34.V26(PRG0_PRU0_GPO9)
PRG0_PRU0GPO10: J18.18 U34.U25(PRG0_PRU0_GPO10)
PRG0_PRU0GPO11: J18.13 R568.2
PRG0_PRU0GPO12: J18.15 RA15.4
PRG0_PRU0GPO13: J18.9 RA15.3
PRG0_PRU0GPO14: J18.11 RA15.2
PRG0_PRU0GPO15: J18.7 RA15.1
PRG0_PRU0GPO16: R569.1 R570.1 U34.AD28(PRG0_PRU0_GPO16)
PRG0_PRU0GPO17: R589.1 R590.1 U34.U26(PRG0_PRU0_GPO17)
PRG0_PRU0GPO18: J18.14 U34.V25(PRG0_PRU0_GPO18)
PRG0_PRU0GPO19: J18.12 U34.U24(PRG0_PRU0_GPO19)
PRG0_PRU1GPO0: R575.1 R576.1 U34.AB28(PRG0_PRU1_GPO0)
PRG0_PRU1GPO1: R579.1 R580.1 U34.AC28(PRG0_PRU1_GPO1)
PRG0_PRU1GPO2: R577.1 R578.1 U34.AC27(PRG0_PRU1_GPO2)
PRG0_PRU1GPO3: R573.1 R574.1 U34.AB26(PRG0_PRU1_GPO3)
PRG0_PRU1GPO4: R571.1 R572.1 U34.AA25(PRG0_PRU1_GPO4)
PRG0_PRU1GPO5: R587.1 R588.1 U34.U23(PRG0_PRU1_GPO5)
PRG0_PRU1GPO6: J18.54 U34.AB27(PRG0_PRU1_GPO6)
PRG0_PRU1GPO7: J18.41 U34.W28(PRG0_PRU1_GPO7)
PRG0_PRU1GPO8: J18.22 U34.W27(PRG0_PRU1_GPO8)
PRG0_PRU1GPO9: J18.45 U34.Y28(PRG0_PRU1_GPO9)
PRG0_PRU1GPO10: J18.49 U34.AA28(PRG0_PRU1_GPO10)
PRG0_PRU1GPO11: J18.48 R527.2
PRG0_PRU1GPO11_R: R527.1 U34.AB24(PRG0_PRU1_GPO11)
PRG0_PRU1GPO12: J18.50 R528.2
PRG0_PRU1GPO12_R: R528.1 U34.AC25(PRG0_PRU1_GPO12)
PRG0_PRU1GPO13: J18.46 RA16.4
PRG0_PRU1GPO13_R: RA16.5 U34.AD25(PRG0_PRU1_GPO13)
PRG0_PRU1GPO14: J18.44 RA16.3
PRG0_PRU1GPO14_R: RA16.6 U34.AD24(PRG0_PRU1_GPO14)
PRG0_PRU1GPO15: J18.42 RA16.2
PRG0_PRU1GPO15_R: RA16.7 U34.AE27(PRG0_PRU1_GPO15)
PRG0_PRU1GPO16: J18.38 RA16.1
PRG0_PRU1GPO16_R: RA16.8 U34.AC24(PRG0_PRU1_GPO16)
PRG0_PRU1GPO17: J18.24 U34.Y27(PRG0_PRU1_GPO17)
PRG0_PRU1GPO18: J18.51 U34.Y26(PRG0_PRU1_GPO18)
PRG0_PRU1GPO19: J18.47 U34.W26(PRG0_PRU1_GPO19)
PRG0_RGMII1_ETH1_CLK: J18.4 ; also on sheet 36
PRG0_RGMII2_ETH2_CLK: J18.106 ; also on sheet 36
PRG1_MDIODATA: J18.99 R605.1 U34.AD18(PRG1_MDIO0_MDIO)
PRG1_MDIOMDCLK: J18.95 U34.AH18(PRG1_MDIO0_MDC)
PRG1_PRU0_GPO11_R: R508.1 U34.AF21(PRG1_PRU0_GPO11)
PRG1_PRU0_GPO12_R: RA13.5 U34.AH20(PRG1_PRU0_GPO12)
PRG1_PRU0_GPO13_R: RA13.6 U34.AH21(PRG1_PRU0_GPO13)
PRG1_PRU0_GPO14_R: RA13.7 U34.AG20(PRG1_PRU0_GPO14)
PRG1_PRU0_GPO15_R: RA13.8 U34.AD19(PRG1_PRU0_GPO15)
PRG1_PRU0GPO0: J18.88 U34.AE22(PRG1_PRU0_GPO0)
PRG1_PRU0GPO1: J18.76 U34.AG24(PRG1_PRU0_GPO1)
PRG1_PRU0GPO2: J18.80 U34.AF23(PRG1_PRU0_GPO2)
PRG1_PRU0GPO3: J18.90 U34.AD21(PRG1_PRU0_GPO3)
PRG1_PRU0GPO4: J18.78 U34.AG23(PRG1_PRU0_GPO4)
PRG1_PRU0GPO5: J18.60 U34.AF27(PRG1_PRU0_GPO5)
PRG1_PRU0GPO6: J18.84 U34.AF22(PRG1_PRU0_GPO6)
PRG1_PRU0GPO7: J18.66 U34.AG27(PRG1_PRU0_GPO7)
PRG1_PRU0GPO8: J18.58 U34.AF28(PRG1_PRU0_GPO8)
PRG1_PRU0GPO9: J18.62 U34.AF26(PRG1_PRU0_GPO9)
PRG1_PRU0GPO10: J18.74 U34.AH25(PRG1_PRU0_GPO10)
PRG1_PRU0GPO11: J18.98 R508.2
PRG1_PRU0GPO12: J18.110 RA13.4
PRG1_PRU0GPO13: J18.114 RA13.3
PRG1_PRU0GPO14: J18.100 RA13.2
PRG1_PRU0GPO15: J18.102 RA13.1
PRG1_PRU0GPO16: J18.94 U34.AD20(PRG1_PRU0_GPO16)
PRG1_PRU0GPO17: J18.70 U34.AH26(PRG1_PRU0_GPO17)
PRG1_PRU0GPO18: J18.72 U34.AG25(PRG1_PRU0_GPO18)
PRG1_PRU0GPO19: J18.68 U34.AG26(PRG1_PRU0_GPO19)
PRG1_PRU1GPO0: J18.63 U34.AH24(PRG1_PRU1_GPO0)
PRG1_PRU1GPO1: J18.67 U34.AH23(PRG1_PRU1_GPO1)
PRG1_PRU1GPO2: J18.77 U34.AG21(PRG1_PRU1_GPO2)
PRG1_PRU1GPO3: J18.75 U34.AH22(PRG1_PRU1_GPO3)
PRG1_PRU1GPO4: J18.65 U34.AE21(PRG1_PRU1_GPO4)
PRG1_PRU1GPO5: J18.55 U34.AC22(PRG1_PRU1_GPO5)
PRG1_PRU1GPO6: J18.71 U34.AG22(PRG1_PRU1_GPO6)
PRG1_PRU1GPO8: J18.57 U34.AE24(PRG1_PRU1_GPO8)
PRG1_PRU1GPO9: J18.64 U34.AF25(PRG1_PRU1_GPO9)
PRG1_PRU1GPO10: J18.61 U34.AF24(PRG1_PRU1_GPO10)
PRG1_PRU1GPO11: J18.81 R499.2
PRG1_PRU1GPO11_R: R499.1 U34.AC20(PRG1_PRU1_GPO11)
PRG1_PRU1GPO12: J18.79 R505.2
PRG1_PRU1GPO12_R: R505.1 U34.AE20(PRG1_PRU1_GPO12)
PRG1_PRU1GPO13: J18.91 RA12.4
PRG1_PRU1GPO13_R: RA12.5 U34.AF19(PRG1_PRU1_GPO13)
PRG1_PRU1GPO14: J18.93 RA12.3
PRG1_PRU1GPO14_R: RA12.6 U34.AH19(PRG1_PRU1_GPO14)
PRG1_PRU1GPO15: J18.83 RA12.2
PRG1_PRU1GPO15_R: RA12.7 U34.AG19(PRG1_PRU1_GPO15)
PRG1_PRU1GPO16: J18.87 RA12.1
PRG1_PRU1GPO16_R: RA12.8 U34.AE19(PRG1_PRU1_GPO16)
PRG1_RGMII1_ETH1_CLK: J18.3 ; also on sheet 36
PRG1_RGMII2_ETH2_CLK: J18.103 ; also on sheet 36
PRG2_ETH1_LED_LINK/MCUBOOTMODE5: U34.Y2(MCU_SPI0_D1) ; also on sheet 21 25
PRG2_ETH2_LED_LINK/MCUBOOTMODE8: U34.AC5(WKUP_GPIO0_8) ; also on sheet 22 25
PRG2_RGMII_INTn_3V3: U34.A22(EXT_REFCLK1) ; also on sheet 38
RESETSTATZ: R779.2 TP48.1(TP) U34.D19(RESETSTATZ) ; also on sheet 18
SoC_DVDD3V3: R395.2 ; also on sheet 13 14 26
SoC_EMU0: U34.AA2(EMU0) ; also on sheet 28
SoC_EMU1: U34.AA1(EMU1) ; also on sheet 28
SOC_I2C0_SCL: J16.21 R586.2 U34.D20(I2C0_SCL) ; also on sheet 11 37 38
SOC_I2C0_SDA: J16.23 R585.2 U34.C21(I2C0_SDA) ; also on sheet 11 37 38
SOC_I2C1_SCL: J44.3 R581.2 TP67.1(TP) U34.B21(I2C1_SCL) ; also on sheet 35
SOC_I2C1_SDA: J45.3 R582.2 TP68.1(TP) U34.E21(I2C1_SDA) ; also on sheet 35
SOC_MAIN_UART0_CTS_3V3: U34.AG11(UART0_CTSN) ; also on sheet 31
SOC_MAIN_UART0_RTS_3V3: U34.AD11(UART0_RTSN) ; also on sheet 31
SOC_MAIN_UART0_RX_3V3: U34.AF11(UART0_RXD) ; also on sheet 31
SOC_MAIN_UART0_TX_3V3: U34.AE11(UART0_TXD) ; also on sheet 31
SOC_MAIN_UART1_RX_1V8: U34.AE23(PRG1_PRU1_GPO17) ; also on sheet 31
SOC_MAIN_UART1_TX_1V8: U34.AD23(PRG1_PRU1_GPO7) ; also on sheet 31
SOC_MCU_SCL: J44.2 R545.2 TP69.1(TP) ; also on sheet 20 35 44
SOC_MCU_SCL_R: J44.1 U34.AD8(MCU_I2C0_SCL)
SOC_MCU_SDA: J45.2 R538.2 TP70.1(TP) ; also on sheet 20 35 44
SOC_MCU_SDA_R: J45.1 U34.AD7(MCU_I2C0_SDA)
SoC_PORz: R427.1 U34.E19(PORZ) U34.W5(MCU_PORZ) ; also on sheet 35 39
SoC_SAFETY_ERRORz: J16.10 TP57.1(TP) U34.E20(SOC_SAFETY_ERRORN)
SOC_SPI0_CLK: J16.20 R491.1 ; also on sheet 19
SOC_SPI0_CLK_R: R491.2 U34.AH13(SPI0_CLK)
SOC_SPI0_CS0: U34.AG13(SPI0_CS0) ; also on sheet 19
SOC_SPI0_CS1: J16.24 U34.AF13(SPI0_CS1)
SOC_SPI0_D0: J16.26 U34.AE13(SPI0_D0) ; also on sheet 19
SOC_SPI0_D1: J16.28 U34.AD13(SPI0_D1) ; also on sheet 19
SOC_SPI1_CLK: R489.1 ; also on sheet 35 38 44
SOC_SPI1_CLK_R: R489.2 U34.AH12(SPI1_CLK)
SOC_SPI1_CS0: U34.AD12(SPI1_CS0) ; also on sheet 35 38
SOC_SPI1_CS1: U34.AG12(SPI1_CS1) ; also on sheet 38 44
SOC_SPI1_MISO: U34.AF12(SPI1_D1) ; also on sheet 35 38 44
SOC_SPI1_MOSI: U34.AE12(SPI1_D0) ; also on sheet 35 38 44
SoC_TCK: U34.AA4(TCK) ; also on sheet 28
SoC_TDI: U34.C20(TDI) ; also on sheet 28
SoC_TDO: R208.2 ; also on sheet 28
SoC_TMS: U34.A21(TMS) ; also on sheet 28
SoC_TRST#: U34.AA3(TRSTN) ; also on sheet 28
SOC_UART1_CTS_1V8: U34.AD22(PRG1_PRU1_GPO18) ; also on sheet 31
SOC_UART1_RTS_1V8: U34.AC21(PRG1_PRU1_GPO19) ; also on sheet 31
SoC_WARM_RESETZ: U34.F17(RESETZ) ; also on sheet 11
SOC_WKUP_SCL: J16.15 R584.2 TP71.1(TP) U34.AC7(WKUP_I2C0_SCL) ; also on sheet 20 35 41 44
SOC_WKUP_SDA: J16.17 R583.2 TP72.1(TP) U34.AD6(WKUP_I2C0_SDA) ; also on sheet 20 35 41 44
SOC_WKUP_UART0_CTS_3V3: U34.AC2(WKUP_GPIO0_6) ; also on sheet 31
SOC_WKUP_UART0_RTS_3V3: U34.AC1(WKUP_GPIO0_7) ; also on sheet 31 38
SOC_WKUP_UART0_RX_3V3: U34.AB1(WKUP_UART0_RXD) ; also on sheet 31
SOC_WKUP_UART0_TX_3V3: U34.AB5(WKUP_UART0_TXD) ; also on sheet 31 38
TEMP_DIODE_P: TP53.1(TP) U34.W6(TEMP_DIODE_P)
TIMER_IO0: U34.B22(TIMER_IO0) ; also on sheet 38
TIMER_IO1: U34.C23(TIMER_IO1) ; also on sheet 38
VPHY_3V3_FT4232: C331.2 FL10.1 U73.4(VPHY)
VPLL_3V3_FT4232: C324.2 FL9.1 R381.2 U73.9(VPLL)
WKUP_LFOSC_RTC_XIN: U34.AE4(WKUP_LFOSC0_XI) ; also on sheet 11
WKUP_OSC0_XIN_SOC: U34.AD5(WKUP_OSC0_XI) ; also on sheet 11
WKUP_OSC0_XOUT: U34.AE6(WKUP_OSC0_XO) ; also on sheet 11
N15507744: C342.1 U76.2(NR/FB)
N18104656: J8.1 R395.1
N18104659: J8.3 R394.2
N18125073: TP60.1(TP) U34.A27(RSV11)
N18125082: R208.1 U34.A20(TDO)
N18125186: R129.1 U34.AB2(WKUP_GPIO0_11)
N18977103: LD7.2(ANODE) R77.2
N18977129: C337.1 U73.3(OSCO) Y2.2
N18977189: C344.1 U73.2(OSCI) Y2.1
N18977240: LD7.1(CATHODE) U73.60(~{PWREN})
N21549383: R729.1 U34.F18(NMIN)

Not connected (* = marked no-connect by the designer): J16 7 8 11 12 14 16 35 37 39 41 43 45 46 47 48 49 50 51 53; J42 4(ID)*; U15 1(IO1)* 2(IO2)*; U34 AC4(WKUP_LFOSC0_XO); U73 21(ADBUS4)* 22(ADBUS5)* 23(ADBUS6)* 24(ADBUS7)* 30(BDBUS4)* 32(BDBUS5)* 33(BDBUS6)* 34(BDBUS7)* 36(~{SUSPEND}) 43(CDBUS4)* 44(CDBUS5)* 45(CDBUS6)* 46(CDBUS7)* 55(DDBUS4)* 57(DDBUS5)* 58(DDBUS6)* 59(DDBUS7)*; U76 5(NC)*; U79 6(NC1)* 7(NC2)*

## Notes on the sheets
sheet 32
- FT4232 UART
- USB Micro B
- GREEN
- FT4232: 5V to 3.3V@500mA LDO
- EEPROM
sheet 33
- APPLICATION BOARD INTERFACE
- 0- Ohm Res MUX between APPLICATION Board connector   and HDMI / GPMC Daughter card.
  -For  APPLICATION Board connector   R570 , R589 ,R576 ,R580 ,R578, R574 ,R572 & R587  Should
  be installed and R569, R590, R575, R579 ,R577 , R573, R571 & R588 Should be DNI'd.
  -For  HDMI / GPMC Daughter card  R569, R590, R575, R579 ,R577 , R573, R571 & R588   Should be
  Installed and   R570 , R589 ,R576 ,R580 ,R578, R574 ,R572 & R587 Should be DNI'd.
  Customer Note – See Users Guide for more information on DNI resistor alternatives
- APPLICATION BOARD CONNECTORS
- APPLICATION CONNECTOR
- APPLICATION CONNECTOR
- ADC Connector
sheet 34
- GENERAL & MCU_GENERAL
- Jumper to select Internal PORz & External PORz
- To Disable the Internal PORz ,
  Connect the Jumper beween Pin no 1 & 2 of J8.
  To Enable the Internal PORz,
  Connect the Jumper between Pin no 2 & 3 of J8
- MCU BOOTMODE
- Jumper option to connect the peripherals connected on MCU_I2C  to SoC I2C1
